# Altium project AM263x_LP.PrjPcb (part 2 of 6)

## Sheet PROC111_AM263x_2_Clock_Reset_Boot_JTAG.SchDoc
size 431 x 279 mm; Date: Not shown in title block; ApprovedBy: Not shown in title block; CheckedBy: Not shown in title block; Author: Not shown in title block; CompanyName: Not shown in title block; Engineer: Not shown in title block; Organization: Not shown in title block; Address1: Not shown in title block; Address2: Not shown in title block; Address3: Not shown in title block; Address4: Not shown in title block; DocumentNumber: 5; Revision: Use project parameter SCH_Rev; SheetNumber: 5; SheetTotal: 24; PageSetup: Record=PageOptions¦CenterHorizontal=True¦CenterVertical=True¦PrintScale=1.00¦XCorrection=1.00¦YCorrection=1.00¦PrintKind=0¦BorderSize=5000000¦LeftOffset=0¦BottomOffset=0¦Orientation=2¦PaperLength=1000¦PaperWidth=1000¦Scale=100¦PaperSource=15¦PrintQuality=600¦MediaType=1¦DitherType=10¦PaperKind=Letter¦PrintScaleMode=1
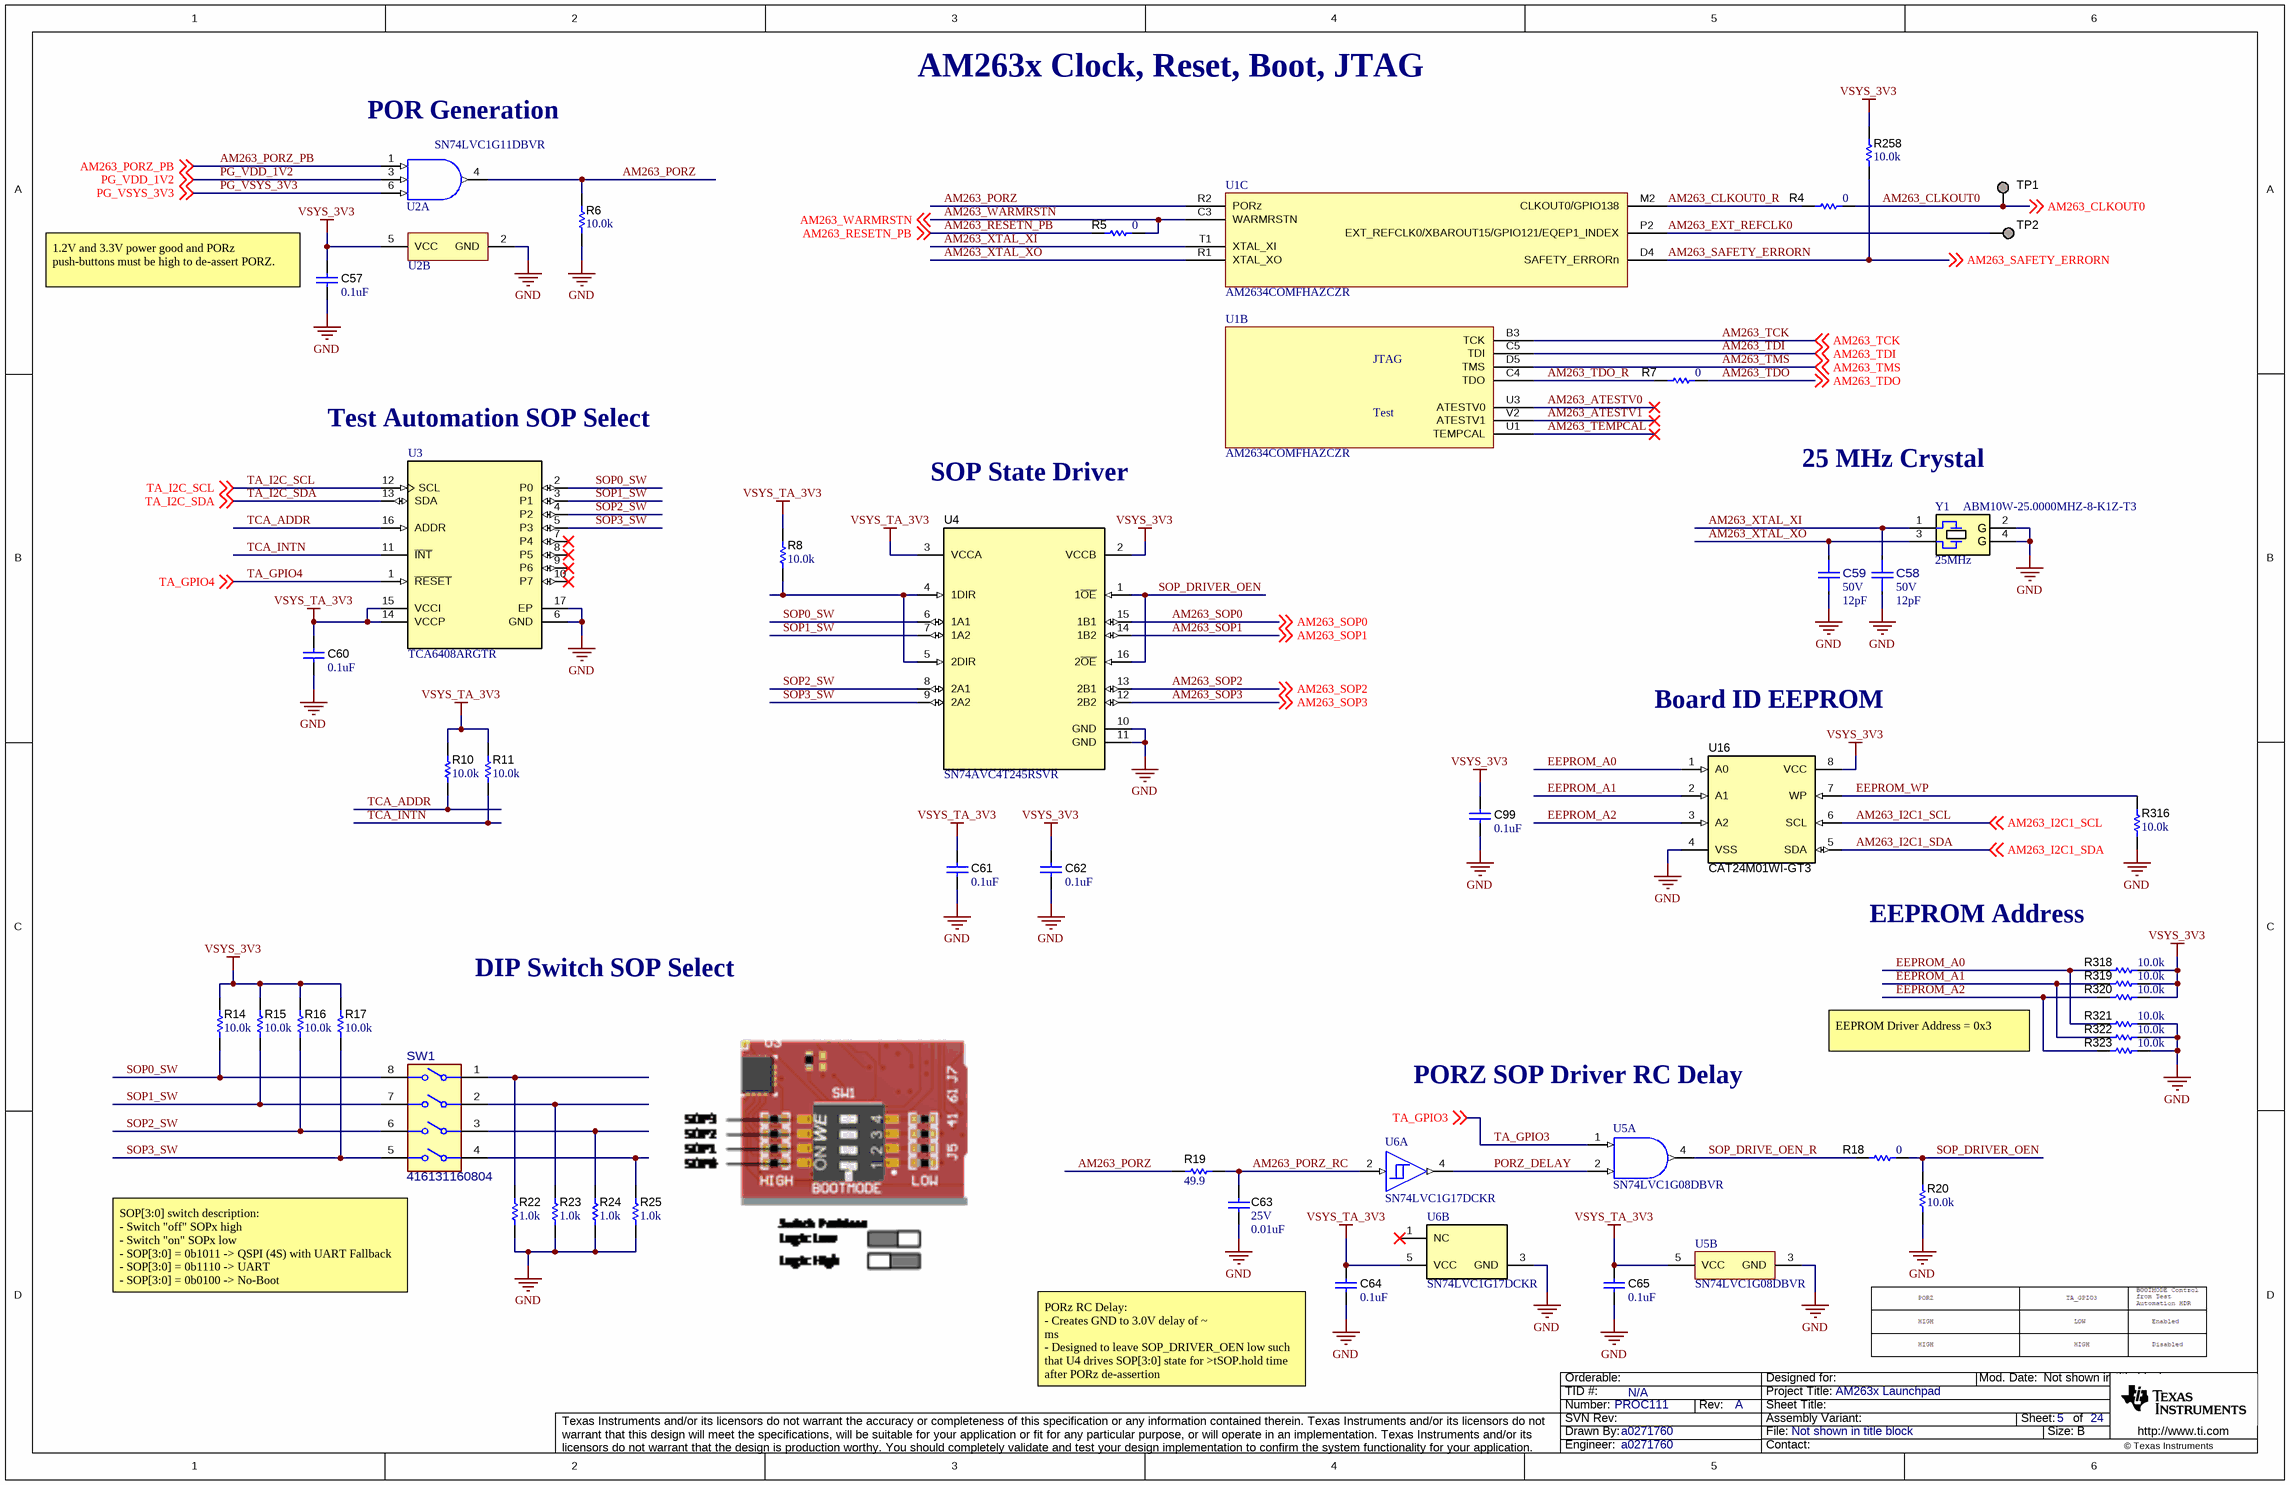
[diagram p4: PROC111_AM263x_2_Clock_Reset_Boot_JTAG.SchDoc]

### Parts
C57  ValueDisplayed: 0.1uF  [0402]  (hidden comment: GRM155R71E104KE14D)
C58  VDC_V: 50V  ValueDisplayed: 12pF  [FP-GRT1555C1H120JA02D_0402-MFG]  (hidden comment: GRT1555C1H120JA02D)
C59  VDC_V: 50V  ValueDisplayed: 12pF  [FP-GRT1555C1H120JA02D_0402-MFG]  (hidden comment: GRT1555C1H120JA02D)
C60  ValueDisplayed: 0.1uF  [0402]  (hidden comment: GRM155R71E104KE14D)
C61  ValueDisplayed: 0.1uF  [0402]  (hidden comment: GRM155R71E104KE14D)
C62  ValueDisplayed: 0.1uF  [0402]  (hidden comment: GRM155R71E104KE14D)
C63  VDC_V: 25V  ValueDisplayed: 0.01uF  [0402]  (hidden comment: GRM155R71E103KA01D)
C64  ValueDisplayed: 0.1uF  [0402]  (hidden comment: GRM155R71E104KE14D)
C65  ValueDisplayed: 0.1uF  [0402]  (hidden comment: GRM155R71E104KE14D)
C99  ValueDisplayed: 0.1uF  [0402]  (hidden comment: GRM155R71E104KE14D)
R4  value 0  [0402L]  (hidden comment: ERJ-2GE0R00X)
R5  ValueDisplayed: 0  [0402]  (hidden comment: ERJ-2GE0R00X)
R6  ValueDisplayed: 10.0k  [0402]  (hidden comment: ERJ-2RKF1002X)
R7  value 0  [0402L]  (hidden comment: ERJ-2GE0R00X)
R8  ValueDisplayed: 10.0k  [0402]  (hidden comment: ERJ-2RKF1002X)
R10  ValueDisplayed: 10.0k  [0402]  (hidden comment: ERJ-2RKF1002X)
R11  ValueDisplayed: 10.0k  [0402]  (hidden comment: ERJ-2RKF1002X)
R14  ValueDisplayed: 10.0k  [0402]  (hidden comment: ERJ-2RKF1002X)
R15  ValueDisplayed: 10.0k  [0402]  (hidden comment: ERJ-2RKF1002X)
R16  ValueDisplayed: 10.0k  [0402]  (hidden comment: ERJ-2RKF1002X)
R17  ValueDisplayed: 10.0k  [0402]  (hidden comment: ERJ-2RKF1002X)
R18  ValueDisplayed: 0  [0402]  (hidden comment: ERJ-2GE0R00X)
R19  ValueDisplayed: 49.9  [0402]  (hidden comment: ERJ-2RKF49R9X)
R20  ValueDisplayed: 10.0k  [0402]  (hidden comment: ERJ-2RKF1002X)
R22  ValueDisplayed: 1.0k  [0402]  (hidden comment: ERJ-2GEJ102X)
R23  ValueDisplayed: 1.0k  [0402]  (hidden comment: ERJ-2GEJ102X)
R24  ValueDisplayed: 1.0k  [0402]  (hidden comment: ERJ-2GEJ102X)
R25  ValueDisplayed: 1.0k  [0402]  (hidden comment: ERJ-2GEJ102X)
R258  ValueDisplayed: 10.0k  [0402]  (hidden comment: ERJ-2RKF1002X)
R316  ValueDisplayed: 10.0k  [0402]  (hidden comment: ERJ-2RKF1002X)
R318  ValueDisplayed: 10.0k  [0402]  (hidden comment: ERJ-2RKF1002X)
R319  ValueDisplayed: 10.0k  [0402]  (hidden comment: ERJ-2RKF1002X)
R320  ValueDisplayed: 10.0k  [0402]  (hidden comment: ERJ-2RKF1002X)
R321  ValueDisplayed: 10.0k  [0402]  (hidden comment: ERJ-2RKF1002X)
R322  ValueDisplayed: 10.0k  [0402]  (hidden comment: ERJ-2RKF1002X)
R323  ValueDisplayed: 10.0k  [0402]  (hidden comment: ERJ-2RKF1002X)
SW1  416131160804  [FP-416131160804_SMT_SW-MFG]
TP1  TP_SM_1MM  [TP_SM_1MM]  (value not drawn)  (no BOM)
TP2  TP_SM_1MM  [TP_SM_1MM]  (value not drawn)  (no BOM)
U1  AM2634COMFHAZCZR  [ZCZ (S-PBGA-N324)]  (parts B,C of 13)
U2  SN74LVC1G11DBVR  [DBV0006A_N]  (parts A,B of 2)
U3  TCA6408ARGTR  [RGT0016A]
U4  SN74AVC4T245RSVR  [RSV0016A]
U5  SN74LVC1G08DBVR  [DBV0005A_N]  (parts A,B of 2)
U6  SN74LVC1G17DCKR  [DCK0005A_N]  (parts A,B of 2)
U16  CAT24M01WI-GT3  [SOIC-8]
Y1  Frequency_Fixed: 25MHz  PartNumber: ABM10W-25.0000MHZ-8-K1Z-T3  [Abracon_ABM10W]  (hidden comment: ABM10W-25.0000MHZ-4-D1X-T3)

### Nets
GND: C57.1 C58.1 C59.1 C60.1 C61.1 C62.1 C63.2 C64.1 C65.1 C99.1 R6.1 R20.2 R22.1 R23.1 R24.1 R25.1 R316.2 R321.1 R322.1 R323.1 U2.2(GND) U3.6(GND) U3.17(EP) U4.10(GND) U4.11(GND) U5.3(GND) U6.3(GND) U16.4(VSS) Y1.2(GND) Y1.4(GND)
VSYS_3V3: C57.2 C62.2 C99.2 R14.1 R15.1 R16.1 R17.1 R258.2 R318.1 R319.1 R320.1 U2.5(VCC) U4.2(VCCB) U16.8(VCC)
VSYS_TA_3V3: C60.2 C61.2 C64.2 C65.2 R8.1 R10.1 R11.1 U3.14(VCCP) U3.15(VCCI) U4.3(VCCA) U5.5(VCC) U6.5(VCC)
AM263_ATESTV0: U1.U3(ATESTV0)
AM263_ATESTV1: U1.V2(ATESTV1)
AM263_CLKOUT0: R4.2 TP1.1 ; off-sheet AM263_CLKOUT0
AM263_CLKOUT0_R: R4.1 U1.M2(CLKOUT0/GPIO138)
AM263_EXT_REFCLK0: TP2.1 U1.P2(EXT_REFCLK0/XBAROUT15/GPIO121/EQEP1_INDEX)
AM263_I2C1_SCL: U16.6(SCL) ; off-sheet AM263_I2C1_SCL
AM263_I2C1_SDA: U16.5(SDA) ; off-sheet AM263_I2C1_SDA
AM263_PORZ: R6.2 R19.1 U1.R2(PORz) U2.4(Y)
AM263_PORZ_PB: U2.1(A) ; off-sheet AM263_PORZ_PB
AM263_PORZ_RC: C63.1 R19.2 U6.2(A)
AM263_RESETN_PB: R5.1 ; off-sheet AM263_RESETN_PB
AM263_SAFETY_ERRORN: R258.1 U1.D4(SAFETY_ERRORn) ; off-sheet AM263_SAFETY_ERRORN
AM263_SOP0: U4.15(1B1) ; off-sheet AM263_SOP0
AM263_SOP1: U4.14(1B2) ; off-sheet AM263_SOP1
AM263_SOP2: U4.13(2B1) ; off-sheet AM263_SOP2
AM263_SOP3: U4.12(2B2) ; off-sheet AM263_SOP3
AM263_TCK: U1.B3(TCK) ; off-sheet AM263_TCK
AM263_TDI: U1.C5(TDI) ; off-sheet AM263_TDI
AM263_TDO: R7.2 ; off-sheet AM263_TDO
AM263_TDO_R: R7.1 U1.C4(TDO)
AM263_TEMPCAL: U1.U1(TEMPCAL)
AM263_TMS: U1.D5(TMS) ; off-sheet AM263_TMS
AM263_WARMRSTN: R5.2 U1.C3(WARMRSTN) ; off-sheet AM263_WARMRSTN
AM263_XTAL_XI: C58.2 U1.T1(XTAL_XI) Y1.1
AM263_XTAL_XO: C59.2 U1.R1(XTAL_XO) Y1.3
EEPROM_A0: R318.2 R321.2 U16.1(A0)
EEPROM_A1: R319.2 R322.2 U16.2(A1)
EEPROM_A2: R320.2 R323.2 U16.3(A2)
EEPROM_WP: R316.1 U16.7(WP)
PG_VDD_1V2: U2.3(B) ; off-sheet PG_VDD_1V2
PG_VSYS_3V3: U2.6(C) ; off-sheet PG_VSYS_3V3
PORZ_DELAY: U5.2(B) U6.4(Y)
SOP0_SW: R14.2 SW1.8 U3.2(P0) U4.6(1A1)
SOP1_SW: R15.2 SW1.7 U3.3(P1) U4.7(1A2)
SOP2_SW: R16.2 SW1.6 U3.4(P2) U4.8(2A1)
SOP3_SW: R17.2 SW1.5 U3.5(P3) U4.9(2A2)
SOP_DRIVE_OEN_R: R18.1 U5.4(Y)
SOP_DRIVER_OEN: R18.2 R20.1 U4.1(1~{OE}) U4.16(2~{OE})
TA_GPIO3: U5.1(A) ; off-sheet TA_GPIO3
TA_GPIO4: U3.1(~{RESET}) ; off-sheet TA_GPIO4
TA_I2C_SCL: U3.12(SCL) ; off-sheet TA_I2C_SCL
TA_I2C_SDA: U3.13(SDA) ; off-sheet TA_I2C_SDA
TCA_ADDR: R10.2 U3.16(ADDR)
TCA_INTN: R11.2 U3.11(~{INT})
NetR8_2: R8.2 U4.4(1DIR) U4.5(2DIR)
NetR22_2: R22.2 SW1.1
NetR23_2: R23.2 SW1.2
NetR24_2: R24.2 SW1.3
NetR25_2: R25.2 SW1.4

Not connected (* = marked no-connect by the designer): U3 7(P4)* 8(P5)* 9(P6)* 10(P7)*; U6 1(NC)*

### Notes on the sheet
- AM263x Clock, Reset, Boot, JTAG
- (near U2) POR Generation
- (near C57) 1.2V and 3.3V power good and PORz push-buttons must be high to de-assert PORZ.
- Test Automation SOP Select
- SOP State Driver
- 25 MHz Crystal
- Board ID EEPROM
- EEPROM Address
- DIP Switch SOP Select
- PORZ SOP Driver RC Delay
- EEPROM Driver Address = 0x3
- (near SW1) SOP[3:0] switch description:
  - Switch "off" SOPx high
  - Switch "on" SOPx low
  - SOP[3:0] = 0b1011 -> QSPI (4S) with UART Fallback
  - SOP[3:0] = 0b1110 -> UART
  - SOP[3:0] = 0b0100 -> No-Boot
- (near C64) PORz RC Delay:
  - Creates GND to 3.0V delay of ~
  ms
  - Designed to leave SOP_DRIVER_OEN low such that U4 drives SOP[3:0] state for >tSOP.hold time after PORz de-assertion

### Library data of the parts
C57 C60-C62 C64 C65 C99 = CMP-0006659-2: CAP, CERM, 0.1 uF, 25 V, +/- 10%, X7R, 0402; Manufacturer: MuRata; TaMin_C: -55°C; Polarized: N; SizeAreaWB_mm2: 3; U/M: EA; Value: 0.1uF; TaMax_C: 125°C; SizeZ_mm: 0.6; SizeX_mm: 1; SizeY_mm: 0.5; Value2: 25V; Cap_F: 100nF; AEC Category: Q200; Value1: Unknown
C58 C59 = CMP-0120209-1: Multi-Layer Ceramic Capacitor 12pF 50V C0G ±5% 0402 Paper T/R; Manufacturer: Murata; TempCo: 30ppm/°C; SizeZ_mm: 0.55mm; AEC Qualified: Yes; AEC Grade: Grade 1
C63 = CMP-0006658-2: CAP, CERM, 0.01 uF, 25 V, +/- 10%, X7R, 0402; Manufacturer: MuRata; TaMin_C: -55°C; Polarized: N; SizeAreaWB_mm2: 3; U/M: EA; Value: 0.01uF; TaMax_C: 125°C; SizeZ_mm: 0.6; SizeX_mm: 1; SizeY_mm: 0.5; Cap_F: 10nF; AEC Category: Q200; Value1: Unknown
R4 R7 = CMP-0026992-3: RES, 0, 5%, 0.1 W, AEC-Q200 Grade 0, 0402; Manufacturer: Panasonic; Power_W: 100mW; TempCo: 600 ppm/C; Value_Code: 0000; EIA_Code: E24; SizeX_mm: 1; SizeY_mm: 0.5; SizeZ_mm: 0.6; Value2: 0.1W; AEC Qualified: Y; VDC_V: 50V; AEC Category: Q200; SizeAreaWB_mm2: 3
R5 R18 = CMP-0026992-3: RES, 0, 5%, 0.1 W, AEC-Q200 Grade 0, 0402; Manufacturer: Panasonic; Power_W: 100mW; TempCo: 600 ppm/C; Value_Code: 0000; Value: 0; EIA_Code: E24; SizeX_mm: 1; SizeY_mm: 0.5; SizeZ_mm: 0.6; Value2: 0.1W; AEC Qualified: Y; VDC_V: 50V; AEC Category: Q200; SizeAreaWB_mm2: 3
R6 R8 R10 R11 R14-R17 R20 R258 R316 R318-R323 = CMP-0026658-1: RES, 10.0 k, 1%, 0.1 W, 0402; Manufacturer: Panasonic; Power_W: 100mW; TempCo: 100 ppm/C; Value_Code: 10k0; U/M: EA; Value: 10.0k; EIA_Code: E96; Res_ohm: 10k; SizeX_mm: 1; SizeY_mm: 0.5; SizeZ_mm: 0.6; Value2: 0.1W; VDC_V: 50V; AEC Category: Q200
R19 = CMP-0026703-1: RES, 49.9, 1%, 0.1 W, AEC-Q200 Grade 0, 0402; Manufacturer: Panasonic; Power_W: 100mW; TempCo: 100 ppm/C; Value_Code: 49R9; U/M: EA; Value: 49.9; EIA_Code: E96; SizeX_mm: 1; SizeY_mm: 0.5; SizeZ_mm: 0.6; Value2: 0.1W; AEC Qualified: Y; VDC_V: 50V; AEC Grade: 0; AEC Category: Q200
R22-R25 = CMP-0078193-1: RES, 1.0 k, 5%, 0.1 W, AEC-Q200 Grade 0, 0402; Manufacturer: Panasonic; Value_Code: 1k00; SizeArea_mm2: 0.5; AEC Qualified: Y; AEC Category: Q200; Res_ohm: 1k; Value: 1.0k; SizeZ_mm: 0.6; Green_REACh: Passed; EIA_Code: E24; TempCo: 200 ppm/C; AEC Grade: 0; Power_W: 100mW; VDC_V: 50V; Value2: 0.1W; Green_Lifecycle: Active; U/M: EA; SizeX_mm: 1
SW1 = CMP-0093176-1: Dip Switch SPST 4 Position Surface Mount Slide (Standard) Actuator 25mA 24VDC; Manufacturer: Wurth; PositionCount: 4; Electromechanical Life: 1000Cycles; Circuit: 4PST; Coil Resistance_ohm: 100mΩ; VDC_V: 24V; Standoff Height: 0mm; SizeZ_mm: 2.65mm; AEC Qualified: No
TP1 TP2 = CMP-0003825-1: 1mm Test Point, SMT; Manufacturer: Any
U1 = AM263x: Sitara AM263x MCU; Manufacturer: Texas Instruments
U2 = CMP-0051219-1: Single 3-Input Positive-AND Gate, DBV0006A, LARGE T&R; Manufacturer: Texas Instruments; Output Type: CMOS; Voltage(Nom)(V): 1.8,2.5,3.3,5; ICC @ Nom Voltage(Max)(mA): 0.01; VCC(Min)(V): 1.65; Output Drive (IOL/IOH)(Max)(mA): 32/-32; Schmitt Trigger: No; Input Type: CMOS/TTL; VCC(Max)(V): 5.5; Gate Type: AND; Rating: Catalog; tpd @ Nom Voltage(Max)(ns): 20,7.8,6.2,4.6; Bits(#): 1; F @ Nom Voltage(Max)(Mhz): 150; Logic: True; Technology Family: LVC
U3 = CMP-0043157-2: Low-Voltage 8-Bit I2C and SMBus I/O Expander, 1.65 to 5.5 V, -40 to 85 degC, 16-pin QFN (RGT), Green (RoHS & no Sb/Br); Manufacturer: Texas Instruments; # of I/Os: 8; I2C Address: 0100 00x; Reset Input: Yes; Max Frequency(kHz): 400; VCC(Max)(V): 5.5; SubFamily: I2C IO Expander; VCC(Min)(V): 1.65
U4 = CMP-0066450-2: 4-Bit Dual-Supply Bus Transceiver with Configurable Voltage-Level Shifting and 3-State Outputs, RSV0016A (UQFN-16); Alternate Manufacturer: Texas Instruments; SizeAreaWB_mm2: 10.08; SizeZ_mm: 0.55; SizeX_mm: 1.8; SizeY_mm: 2.6; SizeArea_mm2: 4.68; CompType: IC; AEC Category: Q200; AEC Qualified: N
U5 = CMP-0051588-2: Single 2-Input Positive-AND Gate, DBV0005A, LARGE T&R; Manufacturer: Texas Instruments; Logic: True; ICC @ Nom Voltage(Max)(mA): 0.01; VCC(Min)(V): 1.65; Bits(#): 1; Rating: Catalog; Schmitt Trigger: No; Voltage(Nom)(V): 1.8,2.5,3.3,5; Output Drive (IOL/IOH)(Max)(mA): 32/-32; Gate Type: AND; tpd @ Nom Voltage(Max)(ns): 4.5,6,4,5; VCC(Max)(V): 5.5; Output Type: CMOS; F @ Nom Voltage(Max)(Mhz): 150; Input Type: CMOS/TTL; Technology Family: LVC; AEC Category: Q200; AEC Qualified: N; CompType: IC
U6 = CMP-0051704-3: Single Schmitt-Trigger Buffer, DCK0005A, LARGE T&R; Manufacturer: Texas Instruments; tpd @ Nom Voltage(Max)(ns): 11,6.5,5.5,5; Bits(#): 1; VCC(Min)(V): 1.65; F @ Nom Voltage(Max)(Mhz): 150; VCC(Max)(V): 5.5; Input Type: CMOS/TTL; Sub-Family: Non-Inverting Buffer/Driver; Output Type: CMOS; Output Drive (IOL/IOH)(Max)(mA): 32/-32; 3-State Output: No; Logic: True; ICC @ Nom Voltage(Max)(mA): 0.01; Voltage(Nom)(V): 1.8,2.5,3.3,5; Rating: Catalog; Schmitt Trigger: Yes; Technology Family: LVC; AEC Category: Q200; AEC Qualified: N; CompType: IC; SizeAreaWB_mm2: 9.3; SizeArea_mm2: 4.2; SizeX_mm: 2.1; SizeY_mm: 2.0; SizeZ_mm: 1.1
U16 = CMP-0005327-2: 1024-Kb I2C CMOS Serial EEPROM, SOIC-8; Manufacturer: ON Semiconductor; SizeAreaWB_mm2: 55.131; SizeZ_mm: 1.75; SizeX_mm: 5.99; SizeY_mm: 4.9; SizeArea_mm2: 29.351
Y1 = CMP-0084811-1: Crystal, 25 MHz, 10 ppm, 4 pF, SMD; Manufacturer: Abracon Corporation; Load Capacitance: 4 pF; TaMax_C: 85°C; SizeY_mm: 2.5; SizeAreaWB_mm2: 10.5; AEC Category: Q200; Frequency Stability: 20 ppm; SizeX_mm: 2; SizeArea_mm2: 5; SizeZ_mm: 0.6; AEC Qualified: N; TaMin_C: -40°C; Frequency Tolerance: 10 ppm

## Sheet PROC111_AM263x_Serial_Connectivity.SchDoc: XDS110 JTAG/USB-to-UART Bridge
size 431 x 279 mm; Date: Not shown in title block; ApprovedBy: Not shown in title block; CheckedBy: Not shown in title block; Author: Not shown in title block; CompanyName: Not shown in title block; Engineer: Not shown in title block; Organization: Not shown in title block; Address1: Not shown in title block; Address2: Not shown in title block; Address3: Not shown in title block; Address4: Not shown in title block; DocumentNumber: 6; Revision: Use project parameter SCH_Rev; SheetNumber: 6; SheetTotal: 24; PageSetup: Record=PageOptions¦CenterHorizontal=True¦CenterVertical=True¦PrintScale=1.00¦XCorrection=1.00¦YCorrection=1.00¦PrintKind=0¦BorderSize=5000000¦LeftOffset=0¦BottomOffset=0¦Orientation=2¦PaperLength=1000¦PaperWidth=1000¦Scale=100¦PaperSource=15¦PrintQuality=600¦MediaType=1¦DitherType=10¦PaperKind=Letter¦PrintScaleMode=1
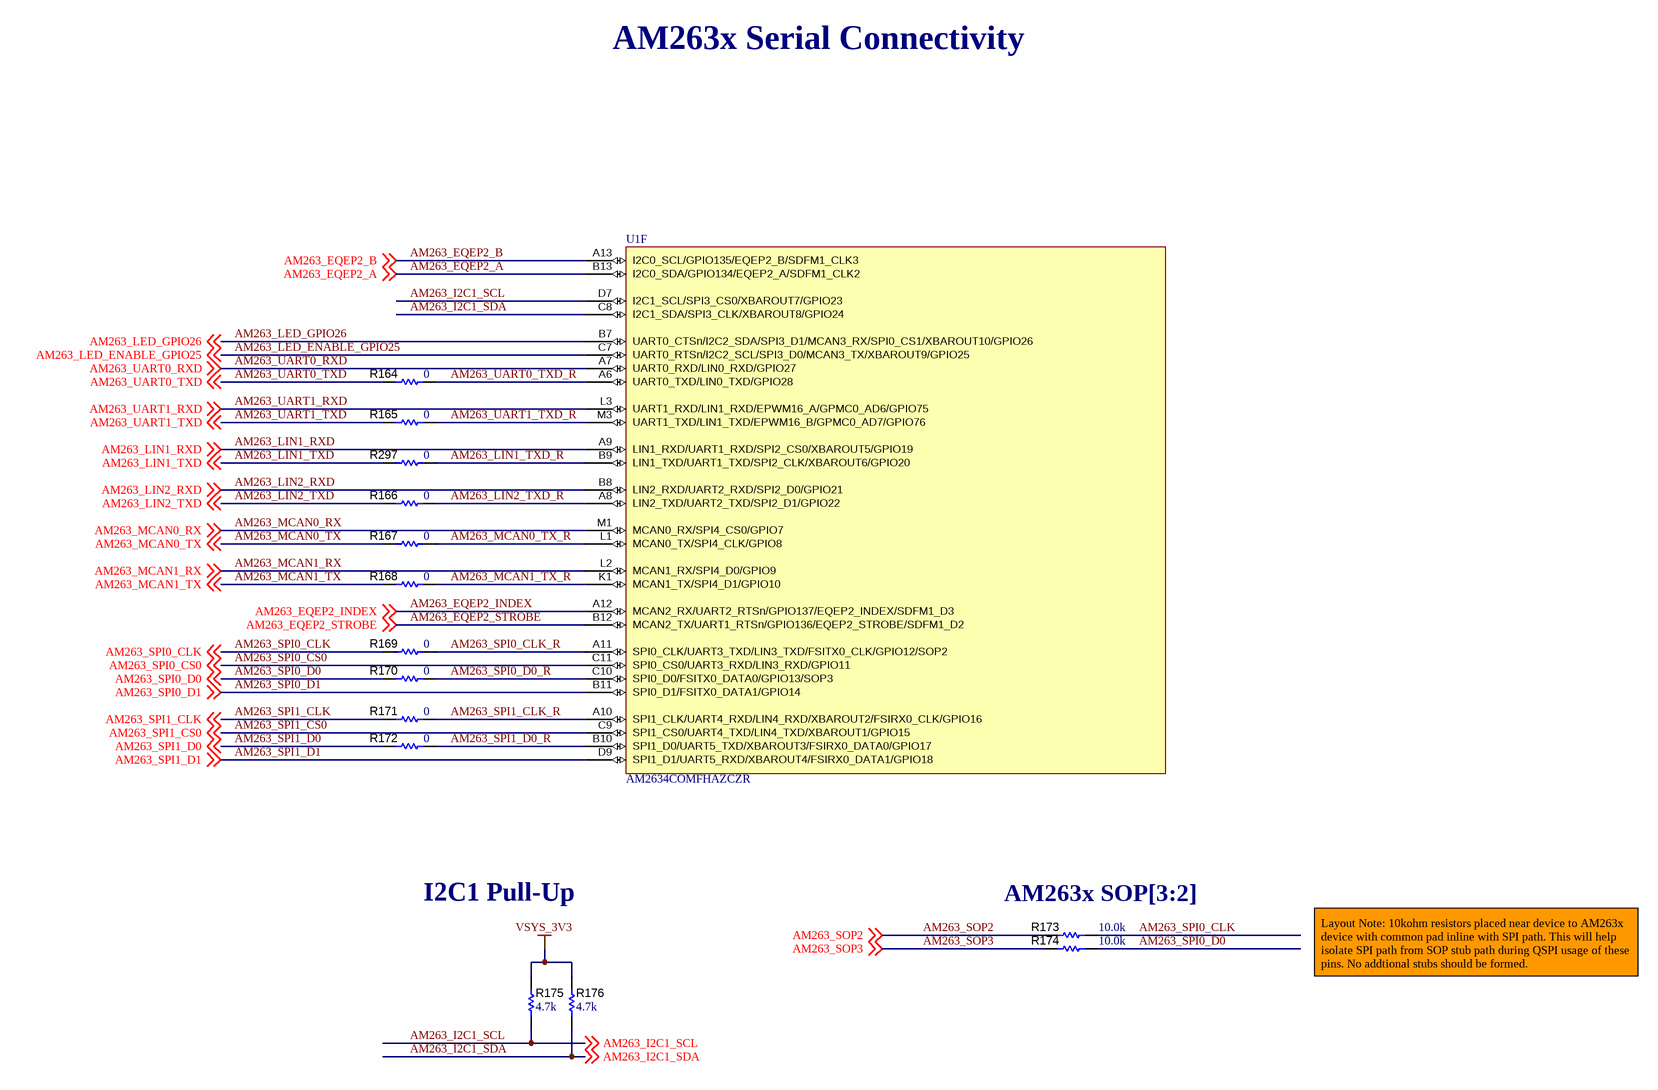
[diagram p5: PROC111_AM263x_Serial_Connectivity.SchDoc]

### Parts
R164  value 0  [0402L]  (hidden comment: ERJ-2GE0R00X)
R165  value 0  [0402L]  (hidden comment: ERJ-2GE0R00X)
R166  value 0  [0402L]  (hidden comment: ERJ-2GE0R00X)
R167  value 0  [0402L]  (hidden comment: ERJ-2GE0R00X)
R168  value 0  [0402L]  (hidden comment: ERJ-2GE0R00X)
R169  value 0  [0402L]  (hidden comment: ERJ-2GE0R00X)
R170  value 0  [0402L]  (hidden comment: ERJ-2GE0R00X)
R171  value 0  [0402L]  (hidden comment: ERJ-2GE0R00X)
R172  value 0  [0402L]  (hidden comment: ERJ-2GE0R00X)
R173  ValueDisplayed: 10.0k  [0402]  (hidden comment: ERJ-2RKF1002X)
R174  ValueDisplayed: 10.0k  [0402]  (hidden comment: ERJ-2RKF1002X)
R175  ValueDisplayed: 4.7k  [0402]  (hidden comment: CRCW04024K70JNED)
R176  ValueDisplayed: 4.7k  [0402]  (hidden comment: CRCW04024K70JNED)
R297  value 0  [0402L]  (hidden comment: ERJ-2GE0R00X)
U1  AM2634COMFHAZCZR  [ZCZ (S-PBGA-N324)]  (part F of 13)

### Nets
VSYS_3V3: R175.2 R176.2
AM263_EQEP2_A: U1.B13(I2C0_SDA/GPIO134/EQEP2_A/SDFM1_CLK2) ; off-sheet AM263_EQEP2_A
AM263_EQEP2_B: U1.A13(I2C0_SCL/GPIO135/EQEP2_B/SDFM1_CLK3) ; off-sheet AM263_EQEP2_B
AM263_EQEP2_INDEX: U1.A12(MCAN2_RX/UART2_RTSn/GPIO137/EQEP2_INDEX/SDFM1_D3) ; off-sheet AM263_EQEP2_INDEX
AM263_EQEP2_STROBE: U1.B12(MCAN2_TX/UART1_RTSn/GPIO136/EQEP2_STROBE/SDFM1_D2) ; off-sheet AM263_EQEP2_STROBE
AM263_I2C1_SCL: R175.1 U1.D7(I2C1_SCL/SPI3_CS0/XBAROUT7/GPIO23) ; off-sheet AM263_I2C1_SCL
AM263_I2C1_SDA: R176.1 U1.C8(I2C1_SDA/SPI3_CLK/XBAROUT8/GPIO24) ; off-sheet AM263_I2C1_SDA
AM263_LED_ENABLE_GPIO25: U1.C7(UART0_RTSn/I2C2_SCL/SPI3_D0/MCAN3_TX/XBAROUT9/GPIO25) ; off-sheet AM263_LED_ENABLE_GPIO25
AM263_LED_GPIO26: U1.B7(UART0_CTSn/I2C2_SDA/SPI3_D1/MCAN3_RX/SPI0_CS1/XBAROUT10/GPIO26) ; off-sheet AM263_LED_GPIO26
AM263_LIN1_RXD: U1.A9(LIN1_RXD/UART1_RXD/SPI2_CS0/XBAROUT5/GPIO19) ; off-sheet AM263_LIN1_RXD
AM263_LIN1_TXD: R297.1 ; off-sheet AM263_LIN1_TXD
AM263_LIN1_TXD_R: R297.2 U1.B9(LIN1_TXD/UART1_TXD/SPI2_CLK/XBAROUT6/GPIO20)
AM263_LIN2_RXD: U1.B8(LIN2_RXD/UART2_RXD/SPI2_D0/GPIO21) ; off-sheet AM263_LIN2_RXD
AM263_LIN2_TXD: R166.1 ; off-sheet AM263_LIN2_TXD
AM263_LIN2_TXD_R: R166.2 U1.A8(LIN2_TXD/UART2_TXD/SPI2_D1/GPIO22)
AM263_MCAN0_RX: U1.M1(MCAN0_RX/SPI4_CS0/GPIO7) ; off-sheet AM263_MCAN0_RX
AM263_MCAN0_TX: R167.1 ; off-sheet AM263_MCAN0_TX
AM263_MCAN0_TX_R: R167.2 U1.L1(MCAN0_TX/SPI4_CLK/GPIO8)
AM263_MCAN1_RX: U1.L2(MCAN1_RX/SPI4_D0/GPIO9) ; off-sheet AM263_MCAN1_RX
AM263_MCAN1_TX: R168.1 ; off-sheet AM263_MCAN1_TX
AM263_MCAN1_TX_R: R168.2 U1.K1(MCAN1_TX/SPI4_D1/GPIO10)
AM263_SOP2: R173.2 ; off-sheet AM263_SOP2
AM263_SOP3: R174.2 ; off-sheet AM263_SOP3
AM263_SPI0_CLK: R169.1 R173.1 ; off-sheet AM263_SPI0_CLK
AM263_SPI0_CLK_R: R169.2 U1.A11(SPI0_CLK/UART3_TXD/LIN3_TXD/FSITX0_CLK/GPIO12/SOP2)
AM263_SPI0_CS0: U1.C11(SPI0_CS0/UART3_RXD/LIN3_RXD/GPIO11) ; off-sheet AM263_SPI0_CS0
AM263_SPI0_D0: R170.1 R174.1 ; off-sheet AM263_SPI0_D0
AM263_SPI0_D0_R: R170.2 U1.C10(SPI0_D0/FSITX0_DATA0/GPIO13/SOP3)
AM263_SPI0_D1: U1.B11(SPI0_D1/FSITX0_DATA1/GPIO14) ; off-sheet AM263_SPI0_D1
AM263_SPI1_CLK: R171.1 ; off-sheet AM263_SPI1_CLK
AM263_SPI1_CLK_R: R171.2 U1.A10(SPI1_CLK/UART4_RXD/LIN4_RXD/XBAROUT2/FSIRX0_CLK/GPIO16)
AM263_SPI1_CS0: U1.C9(SPI1_CS0/UART4_TXD/LIN4_TXD/XBAROUT1/GPIO15) ; off-sheet AM263_SPI1_CS0
AM263_SPI1_D0: R172.1 ; off-sheet AM263_SPI1_D0
AM263_SPI1_D0_R: R172.2 U1.B10(SPI1_D0/UART5_TXD/XBAROUT3/FSIRX0_DATA0/GPIO17)
AM263_SPI1_D1: U1.D9(SPI1_D1/UART5_RXD/XBAROUT4/FSIRX0_DATA1/GPIO18) ; off-sheet AM263_SPI1_D1
AM263_UART0_RXD: U1.A7(UART0_RXD/LIN0_RXD/GPIO27) ; off-sheet AM263_UART0_RXD
AM263_UART0_TXD: R164.1 ; off-sheet AM263_UART0_TXD
AM263_UART0_TXD_R: R164.2 U1.A6(UART0_TXD/LIN0_TXD/GPIO28)
AM263_UART1_RXD: U1.L3(UART1_RXD/LIN1_RXD/EPWM16_A/GPMC0_AD6/GPIO75) ; off-sheet AM263_UART1_RXD
AM263_UART1_TXD: R165.1 ; off-sheet AM263_UART1_TXD
AM263_UART1_TXD_R: R165.2 U1.M3(UART1_TXD/LIN1_TXD/EPWM16_B/GPMC0_AD7/GPIO76)

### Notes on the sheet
- AM263x Serial Connectivity
- I2C1 Pull-Up
- AM263x SOP[3:2]
- Layout Note: 10kohm resistors placed near device to AM263x device with common pad inline with SPI path. This will help isolate SPI path from SOP stub path during QSPI usage of these pins. No addtional stubs should be formed.

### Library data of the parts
R164-R172 R297 = CMP-0026992-3: as R4 on sheet PROC111_AM263x_2_Clock_Reset_Boot_JTAG
R173 R174 = CMP-0026658-1: as R6 on sheet PROC111_AM263x_2_Clock_Reset_Boot_JTAG
R175 R176 = CMP-0026938-5: RES, 4.7 k, 5%, 0.063 W, AEC-Q200 Grade 0, 0402; Manufacturer: Vishay-Dale; Power_W: 63mW; TempCo: 200 ppm/C; Value_Code: 4k70; Value: 4.7k; EIA_Code: E24; SizeX_mm: 1; SizeY_mm: 0.5; SizeZ_mm: 0.6; Value2: 0.063W; AEC Qualified: Y; VDC_V: 50V; AEC Category: Q200; AEC Grade: 0
U1 = AM263x: as U1 on sheet PROC111_AM263x_2_Clock_Reset_Boot_JTAG

## Sheet PROC111_AM263x_3_QSPI_MMC.SchDoc
size 431 x 279 mm; Date: Not shown in title block; ApprovedBy: Not shown in title block; CheckedBy: Not shown in title block; Author: Not shown in title block; CompanyName: Not shown in title block; Engineer: Not shown in title block; Organization: Not shown in title block; Address1: Not shown in title block; Address2: Not shown in title block; Address3: Not shown in title block; Address4: Not shown in title block; DocumentNumber: 7; Revision: Use project parameter SCH_Rev; SheetNumber: 7; SheetTotal: 24; PageSetup: Record=PageOptions¦CenterHorizontal=True¦CenterVertical=True¦PrintScale=1.00¦XCorrection=1.00¦YCorrection=1.00¦PrintKind=0¦BorderSize=5000000¦LeftOffset=0¦BottomOffset=0¦Orientation=2¦PaperLength=1000¦PaperWidth=1000¦Scale=100¦PaperSource=15¦PrintQuality=600¦MediaType=1¦DitherType=10¦PaperKind=Letter¦PrintScaleMode=1
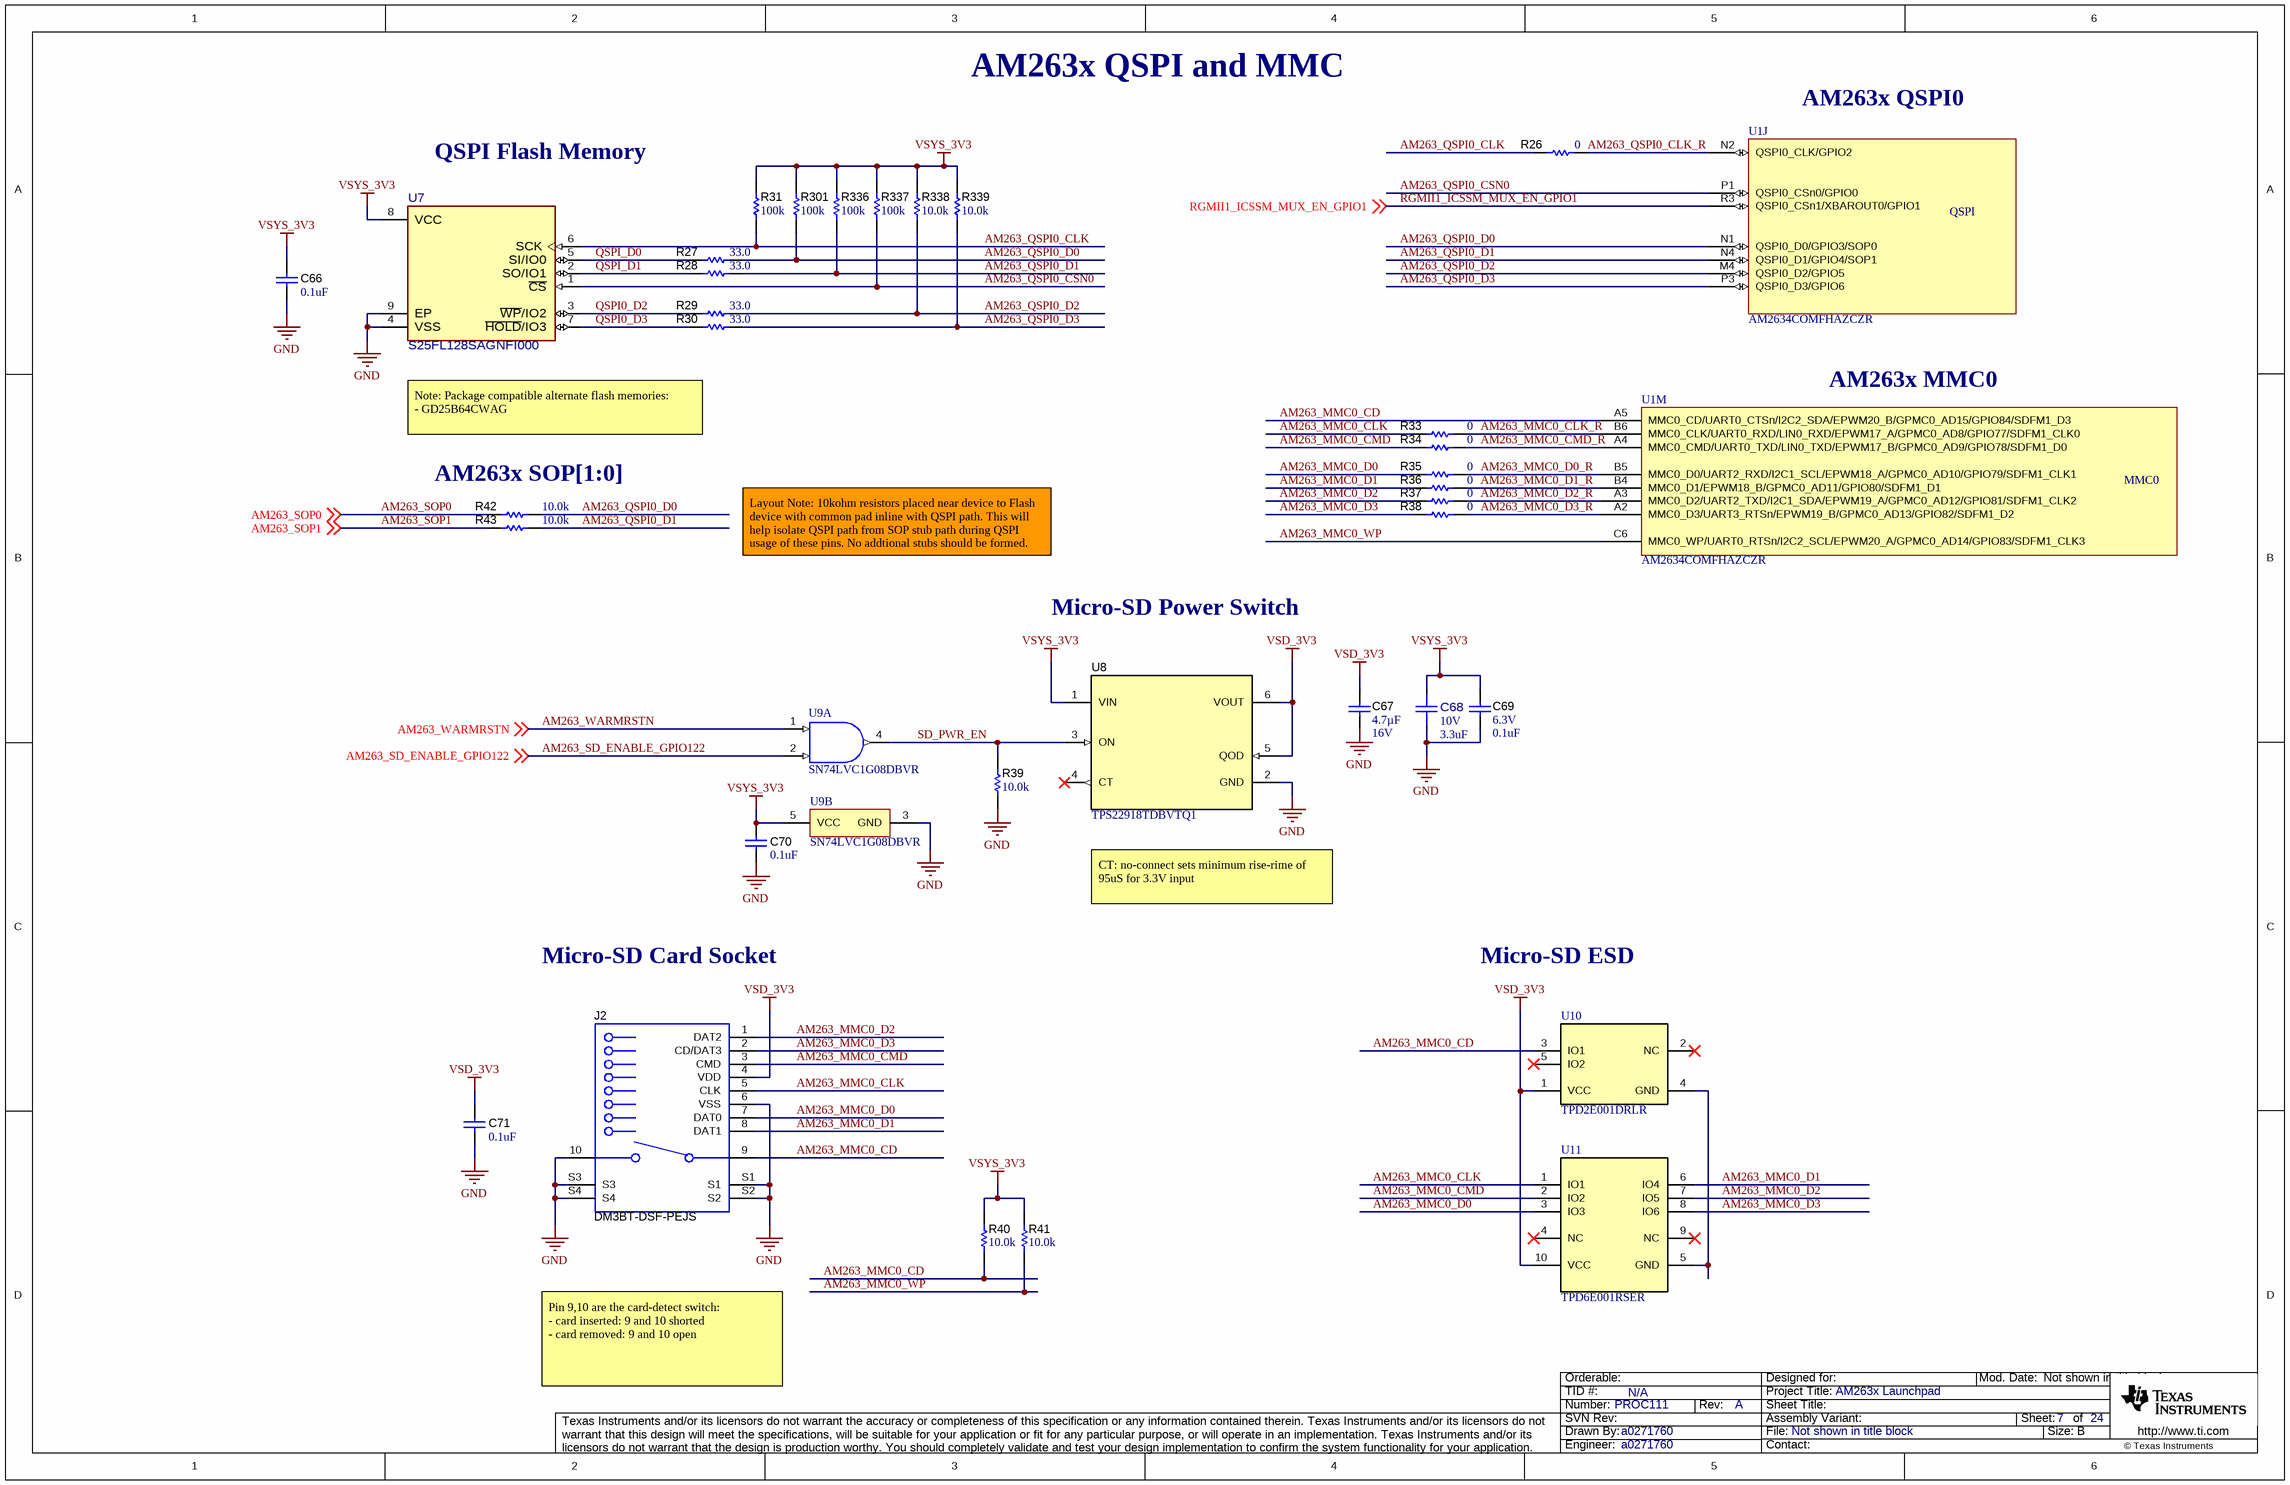
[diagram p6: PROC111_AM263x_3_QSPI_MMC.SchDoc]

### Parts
C66  ValueDisplayed: 0.1uF  [0402]  (hidden comment: GRM155R71E104KE14D)
C67  Cap_F: 4.7µF  VDC_V: 16V  [0603]  (hidden comment: GRM188Z71C475KE21D)
C68  VDC_V: 10V  ValueDisplayed: 3.3uF  [FP-CL10A335KP8NNNC_0603-MFG]  (hidden comment: CL10A335KP8NNNC)
C69  VDC_V: 6.3V  ValueDisplayed: 0.1uF  [0402]  (hidden comment: GRM155R70J104KA01D)
C70  ValueDisplayed: 0.1uF  [0402]  (hidden comment: GRM155R71E104KE14D)
C71  ValueDisplayed: 0.1uF  [0402]  (hidden comment: GRM155R71E104KE14D)
J2  DM3BT-DSF-PEJS  [Hirose_DM3BT-DSF-PEJS]
R26  value 0  [0402L]  (hidden comment: ERJ-2GE0R00X)
R27  ValueDisplayed: 33.0  [0402S]  (hidden comment: ERJ-2RKF33R0X)
R28  ValueDisplayed: 33.0  [0402S]  (hidden comment: ERJ-2RKF33R0X)
R29  ValueDisplayed: 33.0  [0402S]  (hidden comment: ERJ-2RKF33R0X)
R30  ValueDisplayed: 33.0  [0402S]  (hidden comment: ERJ-2RKF33R0X)
R31  ValueDisplayed: 100k  [0402S]  (hidden comment: ERJ-2RKF1003X)
R33  ValueDisplayed: 0  [0402L]  (hidden comment: ERJ-2GE0R00X)
R34  ValueDisplayed: 0  [0402L]  (hidden comment: ERJ-2GE0R00X)
R35  ValueDisplayed: 0  [0402L]  (hidden comment: ERJ-2GE0R00X)
R36  ValueDisplayed: 0  [0402L]  (hidden comment: ERJ-2GE0R00X)
R37  ValueDisplayed: 0  [0402L]  (hidden comment: ERJ-2GE0R00X)
R38  ValueDisplayed: 0  [0402L]  (hidden comment: ERJ-2GE0R00X)
R39  ValueDisplayed: 10.0k  [0402L]  (hidden comment: CRCW040210K0FKED)
R40  ValueDisplayed: 10.0k  [0402L]  (hidden comment: CRCW040210K0FKED)
R41  ValueDisplayed: 10.0k  [0402L]  (hidden comment: CRCW040210K0FKED)
R42  ValueDisplayed: 10.0k  [0402]  (hidden comment: ERJ-2RKF1002X)
R43  ValueDisplayed: 10.0k  [0402]  (hidden comment: ERJ-2RKF1002X)
R301  ValueDisplayed: 100k  [0402S]  (hidden comment: ERJ-2RKF1003X)
R336  ValueDisplayed: 100k  [0402S]  (hidden comment: ERJ-2RKF1003X)
R337  ValueDisplayed: 100k  [0402S]  (hidden comment: ERJ-2RKF1003X)
R338  ValueDisplayed: 10.0k  [0402S]  (hidden comment: CRCW040210K0FKED)
R339  ValueDisplayed: 10.0k  [0402S]  (hidden comment: CRCW040210K0FKED)
U1  AM2634COMFHAZCZR  [ZCZ (S-PBGA-N324)]  (parts J,M of 13)
U7  S25FL128SAGNFI000  [FP-S25FL128SAGNFI000_WSON8-IPC_B]
U8  TPS22918TDBVTQ1  [DBV0006A_N]
U9  SN74LVC1G08DBVR  [DBV0005A_N]  (parts A,B of 2)
U10  TPD2E001DRLR  [DRL0005A]
U11  TPD6E001RSER  [RSE0010A]

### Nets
GND: C66.1 C67.2 C68.1 C69.2 C70.1 C71.1 J2.6(VSS) J2.10(B) J2.S1 J2.S2 J2.S3 J2.S4 R39.1 U7.4(VSS) U7.9(EP) U8.2(GND) U9.3(GND)
VSD_3V3: C67.1 C71.2 J2.4(VDD) U8.5(QOD) U8.6(VOUT) U10.1(VCC) U11.10(VCC)
VSYS_3V3: C66.2 C68.2 C69.1 C70.2 R31.2 R40.2 R41.2 R301.2 R336.2 R337.2 R338.2 R339.2 U7.8(VCC) U8.1(VIN) U9.5(VCC)
AM263_MMC0_CD: J2.9(A) R40.1 U1.A5(MMC0_CD/UART0_CTSn/I2C2_SDA/EPWM20_B/GPMC0_AD15/GPIO84/SDFM1_D3) U10.3(IO1)
AM263_MMC0_CLK: J2.5(CLK) R33.2 U11.1(IO1)
AM263_MMC0_CLK_R: R33.1 U1.B6(MMC0_CLK/UART0_RXD/LIN0_RXD/EPWM17_A/GPMC0_AD8/GPIO77/SDFM1_CLK0)
AM263_MMC0_CMD: J2.3(CMD) R34.2 U11.2(IO2)
AM263_MMC0_CMD_R: R34.1 U1.A4(MMC0_CMD/UART0_TXD/LIN0_TXD/EPWM17_B/GPMC0_AD9/GPIO78/SDFM1_D0)
AM263_MMC0_D0: J2.7(DAT0) R35.2 U11.3(IO3)
AM263_MMC0_D0_R: R35.1 U1.B5(MMC0_D0/UART2_RXD/I2C1_SCL/EPWM18_A/GPMC0_AD10/GPIO79/SDFM1_CLK1)
AM263_MMC0_D1: J2.8(DAT1) R36.2 U11.6(IO4)
AM263_MMC0_D1_R: R36.1 U1.B4(MMC0_D1/EPWM18_B/GPMC0_AD11/GPIO80/SDFM1_D1)
AM263_MMC0_D2: J2.1(DAT2) R37.2 U11.7(IO5)
AM263_MMC0_D2_R: R37.1 U1.A3(MMC0_D2/UART2_TXD/I2C1_SDA/EPWM19_A/GPMC0_AD12/GPIO81/SDFM1_CLK2)
AM263_MMC0_D3: J2.2(CD/DAT3) R38.2 U11.8(IO6)
AM263_MMC0_D3_R: R38.1 U1.A2(MMC0_D3/UART3_RTSn/EPWM19_B/GPMC0_AD13/GPIO82/SDFM1_D2)
AM263_MMC0_WP: R41.1 U1.C6(MMC0_WP/UART0_RTSn/I2C2_SCL/EPWM20_A/GPMC0_AD14/GPIO83/SDFM1_CLK3)
AM263_QSPI0_CLK: R26.1 R31.1 U7.6(SCK)
AM263_QSPI0_CLK_R: R26.2 U1.N2(QSPI0_CLK/GPIO2)
AM263_QSPI0_CSN0: R337.1 U1.P1(QSPI0_CSn0/GPIO0) U7.1(~{CS})
AM263_QSPI0_D0: R27.2 R42.1 R301.1 U1.N1(QSPI0_D0/GPIO3/SOP0)
AM263_QSPI0_D1: R28.2 R43.1 R336.1 U1.N4(QSPI0_D1/GPIO4/SOP1)
AM263_QSPI0_D2: R29.2 R338.1 U1.M4(QSPI0_D2/GPIO5)
AM263_QSPI0_D3: R30.2 R339.1 U1.P3(QSPI0_D3/GPIO6)
AM263_SD_ENABLE_GPIO122: U9.2(B) ; off-sheet AM263_SD_ENABLE_GPIO122
AM263_SOP0: R42.2 ; off-sheet AM263_SOP0
AM263_SOP1: R43.2 ; off-sheet AM263_SOP1
AM263_WARMRSTN: U9.1(A) ; off-sheet AM263_WARMRSTN
QSPI0_D2: R29.1 U7.3(~{WP}/IO2)
QSPI0_D3: R30.1 U7.7(~{HOLD}/IO3)
QSPI_D0: R27.1 U7.5(SI/IO0)
QSPI_D1: R28.1 U7.2(SO/IO1)
RGMII1_ICSSM_MUX_EN_GPIO1: U1.R3(QSPI0_CSn1/XBAROUT0/GPIO1) ; off-sheet RGMII1_ICSSM_MUX_EN_GPIO1
SD_PWR_EN: R39.2 U8.3(ON) U9.4(Y)
NetU10_4: U10.4(GND) U11.5(GND)

Not connected (* = marked no-connect by the designer): U8 4(CT)*; U10 2(NC)* 5(IO2)*; U11 4(NC)* 9(NC)*

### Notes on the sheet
- AM263x QSPI and MMC
- QSPI Flash Memory
- AM263x QSPI0
- Note: Package compatible alternate flash memories:
  - GD25B64CWAG
- AM263x MMC0
- AM263x SOP[1:0]
- Layout Note: 10kohm resistors placed near device to Flash device with common pad inline with QSPI path. This will help isolate QSPI path from SOP stub path during QSPI usage of these pins. No addtional stubs should be formed.
- Micro-SD Power Switch
- CT: no-connect sets minimum rise-rime of 95uS for 3.3V input
- Micro-SD Card Socket
- Micro-SD ESD
- Pin 9,10 are the card-detect switch:
  - card inserted: 9 and 10 shorted
  - card removed: 9 and 10 open

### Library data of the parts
C66 C70 C71 = CMP-0006659-2: as C57 on sheet PROC111_AM263x_2_Clock_Reset_Boot_JTAG
C67 = CMP-0064936-4: CAP, CERM, 4.7 uF, 16 V,+/- 10%, X7R, 0603; Manufacturer: MuRata; TaMin_C: -55°C; Polarized: N; SizeAreaWB_mm2: 4.68; Value1: Unknown; U/M: EA; Value: 4.7uF; TaMax_C: 125°C; SizeZ_mm: 1; SizeX_mm: 1.6; SizeY_mm: 0.8; SizeArea_mm2: 1.28; AEC Category: Q200
C68 = CMP-0042976-1: Cap Ceramic 3.3uF 10V X5R ±10% Pad SMD 0603 +85°C T/R; Manufacturer: Samsung; TempCo: 15%; Value: 3.3µF; SizeZ_mm: 0.9mm; AEC Qualified: No
C69 = CMP-0006623-2: CAP, CERM, 0.1 uF, 6.3 V, +/- 10%, X7R, 0402; Manufacturer: MuRata; TaMin_C: -55°C; Polarized: N; SizeAreaWB_mm2: 3; Value1: Unknown; U/M: EA; Value: 0.1uF; TaMax_C: 125°C; SizeZ_mm: 0.6; SizeX_mm: 1; SizeY_mm: 0.5; Cap_F: 100nF; AEC Category: Q200
J2 = CMP-0080007-1: Conncetor, micro SD, 8+2 Pos, R/A, SMT; Manufacturer: Hirose Electric Co. Ltd.; Pitch_mm: 1.1; Gender: Female; ContactFinish: Gold; Row_Count: 1; CompType: Connector
R26 = CMP-0026992-3: as R4 on sheet PROC111_AM263x_2_Clock_Reset_Boot_JTAG
R27-R30 = CMP-0026696-1: RES, 33.0, 1%, 0.1 W, 0402; Manufacturer: Panasonic; Power_W: 100mW; TempCo: 100 ppm/C; Value_Code: 33R0; U/M: EA; Value: 33.0; Res_ohm: 33; SizeX_mm: 1; SizeY_mm: 0.5; SizeZ_mm: 0.6; Value2: 0.1W; VDC_V: 50V; AEC Category: Q200
R31 R301 R336 R337 = CMP-0026659-2: RES, 100 k, 1%, 0.1 W, 0402; Manufacturer: Panasonic; U/M: EA; Value2: 0.1W; EIA_Code: E96; Value: 100k; SizeArea_mm2: 0.5; TempCo: 100 ppm/C; SizeZ_mm: 0.6; AEC Category: Q200; VDC_V: 50V; Power_W: 100mW; AEC Grade: 0; SizeX_mm: 1; AEC Qualified: Yes
R33-R38 = CMP-0026992-3: as R5 on sheet PROC111_AM263x_2_Clock_Reset_Boot_JTAG
R39-R41 R338 R339 = CMP-0025958-3: RES, 10.0 k, 1%, 0.063 W, AEC-Q200 Grade 0, 0402; Manufacturer: Vishay-Dale; Power_W: 63mW; TempCo: 100 ppm/C; Value_Code: 10k0; Value: 10.0k; EIA_Code: E96; Res_ohm: 10k; SizeX_mm: 1; SizeY_mm: 0.5; SizeZ_mm: 0.6; Value2: 0.063W; AEC Qualified: Y; VDC_V: 50V; AEC Category: Q200; AEC Grade: 0
R42 R43 = CMP-0026658-1: as R6 on sheet PROC111_AM263x_2_Clock_Reset_Boot_JTAG
U1 = AM263x: as U1 on sheet PROC111_AM263x_2_Clock_Reset_Boot_JTAG
U7 = CMP-0093537-1: FLASH - NOR Memory IC 128Mb (16M x 8) SPI - Quad I/O 133 MHz 8-WSON (6x8); Manufacturer: Cypress Semiconductor; Nominal Supply Current: 16-100mA; AEC Qualified: No; Max Supply Voltage: 3.6V; Access Time: 8ns; TaMin_C: -40°C; SizeZ_mm: 0.8mm; TaMax_C: +85°C; Standoff Height: 0mm; Memory Size: 128Mbits; Min Supply Voltage: 1.65V; Frequency_Fixed: 133MHz
U8 = CMP-0081995-1: 5.5V, 2A, 52mΩ Automotive High-Side Load Switch with Adjustable Rise Time & Quick Output Discharge, DBV0006A (SOT-23-6); Alternate PartNumber: TPS22918TDBVRQ1; Alternate Manufacturer: Texas Instruments; SizeAreaWB_mm2: 14.82; SizeZ_mm: 1.45; SizeX_mm: 2.8; SizeY_mm: 2.9; SizeArea_mm2: 8.12; CompType: IC; AEC Qualified: Y; AEC Category: Q200
U9 = CMP-0051588-2: as U5 on sheet PROC111_AM263x_2_Clock_Reset_Boot_JTAG
U10 = CMP-0043096-2: Low-Capacitance + / - 15 kV ESD-Protection Array for High-Speed Data Interfaces, 2 Channels, -40 to +85 degC, 5-pin SOT (DRL), Green (RoHS & no Sb/Br); Manufacturer: Texas Instruments; IO Leakage Current(nA): 1; IO Capacitance(Typ)(pF): 1.5; USB High Speed: TRUE; SubFamily: ESD Solution; Breakdown Voltage(Min)(V): 11; IEC 61000-4-2 Air-Gap(+/- kV): 15; IEC 61000-4-2 Contact(+/- kV): 8
U11 = CMP-0043123-1: Low-Capacitance + / - 15 kV ESD Protection Array for High-Speed Data Interfaces, 6 Channels, -40 to +85 degC, 10-pin UQFN (RSE), Green (RoHS & no Sb/Br); Manufacturer: Texas Instruments; Serial ATA / eSATA: TRUE; IO Leakage Current(nA): 1; IO Capacitance(Typ)(pF): 1.5; IEC 61000-4-2 Contact(+/- kV): 8; Breakdown Voltage(Min)(V): 11; IEC 61000-4-2 Air-Gap(+/- kV): 15; SubFamily: ESD Solution

## Sheet PROC111_AM263x_4_ADC_DAC.SchDoc
size 431 x 279 mm; Date: Not shown in title block; ApprovedBy: Not shown in title block; CheckedBy: Not shown in title block; Author: Not shown in title block; CompanyName: Not shown in title block; Engineer: Not shown in title block; Organization: Not shown in title block; Address1: Not shown in title block; Address2: Not shown in title block; Address3: Not shown in title block; Address4: Not shown in title block; DocumentNumber: 8; Revision: Use project parameter SCH_Rev; SheetNumber: 8; SheetTotal: 24; PageSetup: Record=PageOptions¦CenterHorizontal=True¦CenterVertical=True¦PrintScale=1.00¦XCorrection=1.00¦YCorrection=1.00¦PrintKind=0¦BorderSize=5000000¦LeftOffset=0¦BottomOffset=0¦Orientation=2¦PaperLength=1000¦PaperWidth=1000¦Scale=100¦PaperSource=15¦PrintQuality=600¦MediaType=1¦DitherType=10¦PaperKind=Letter¦PrintScaleMode=1
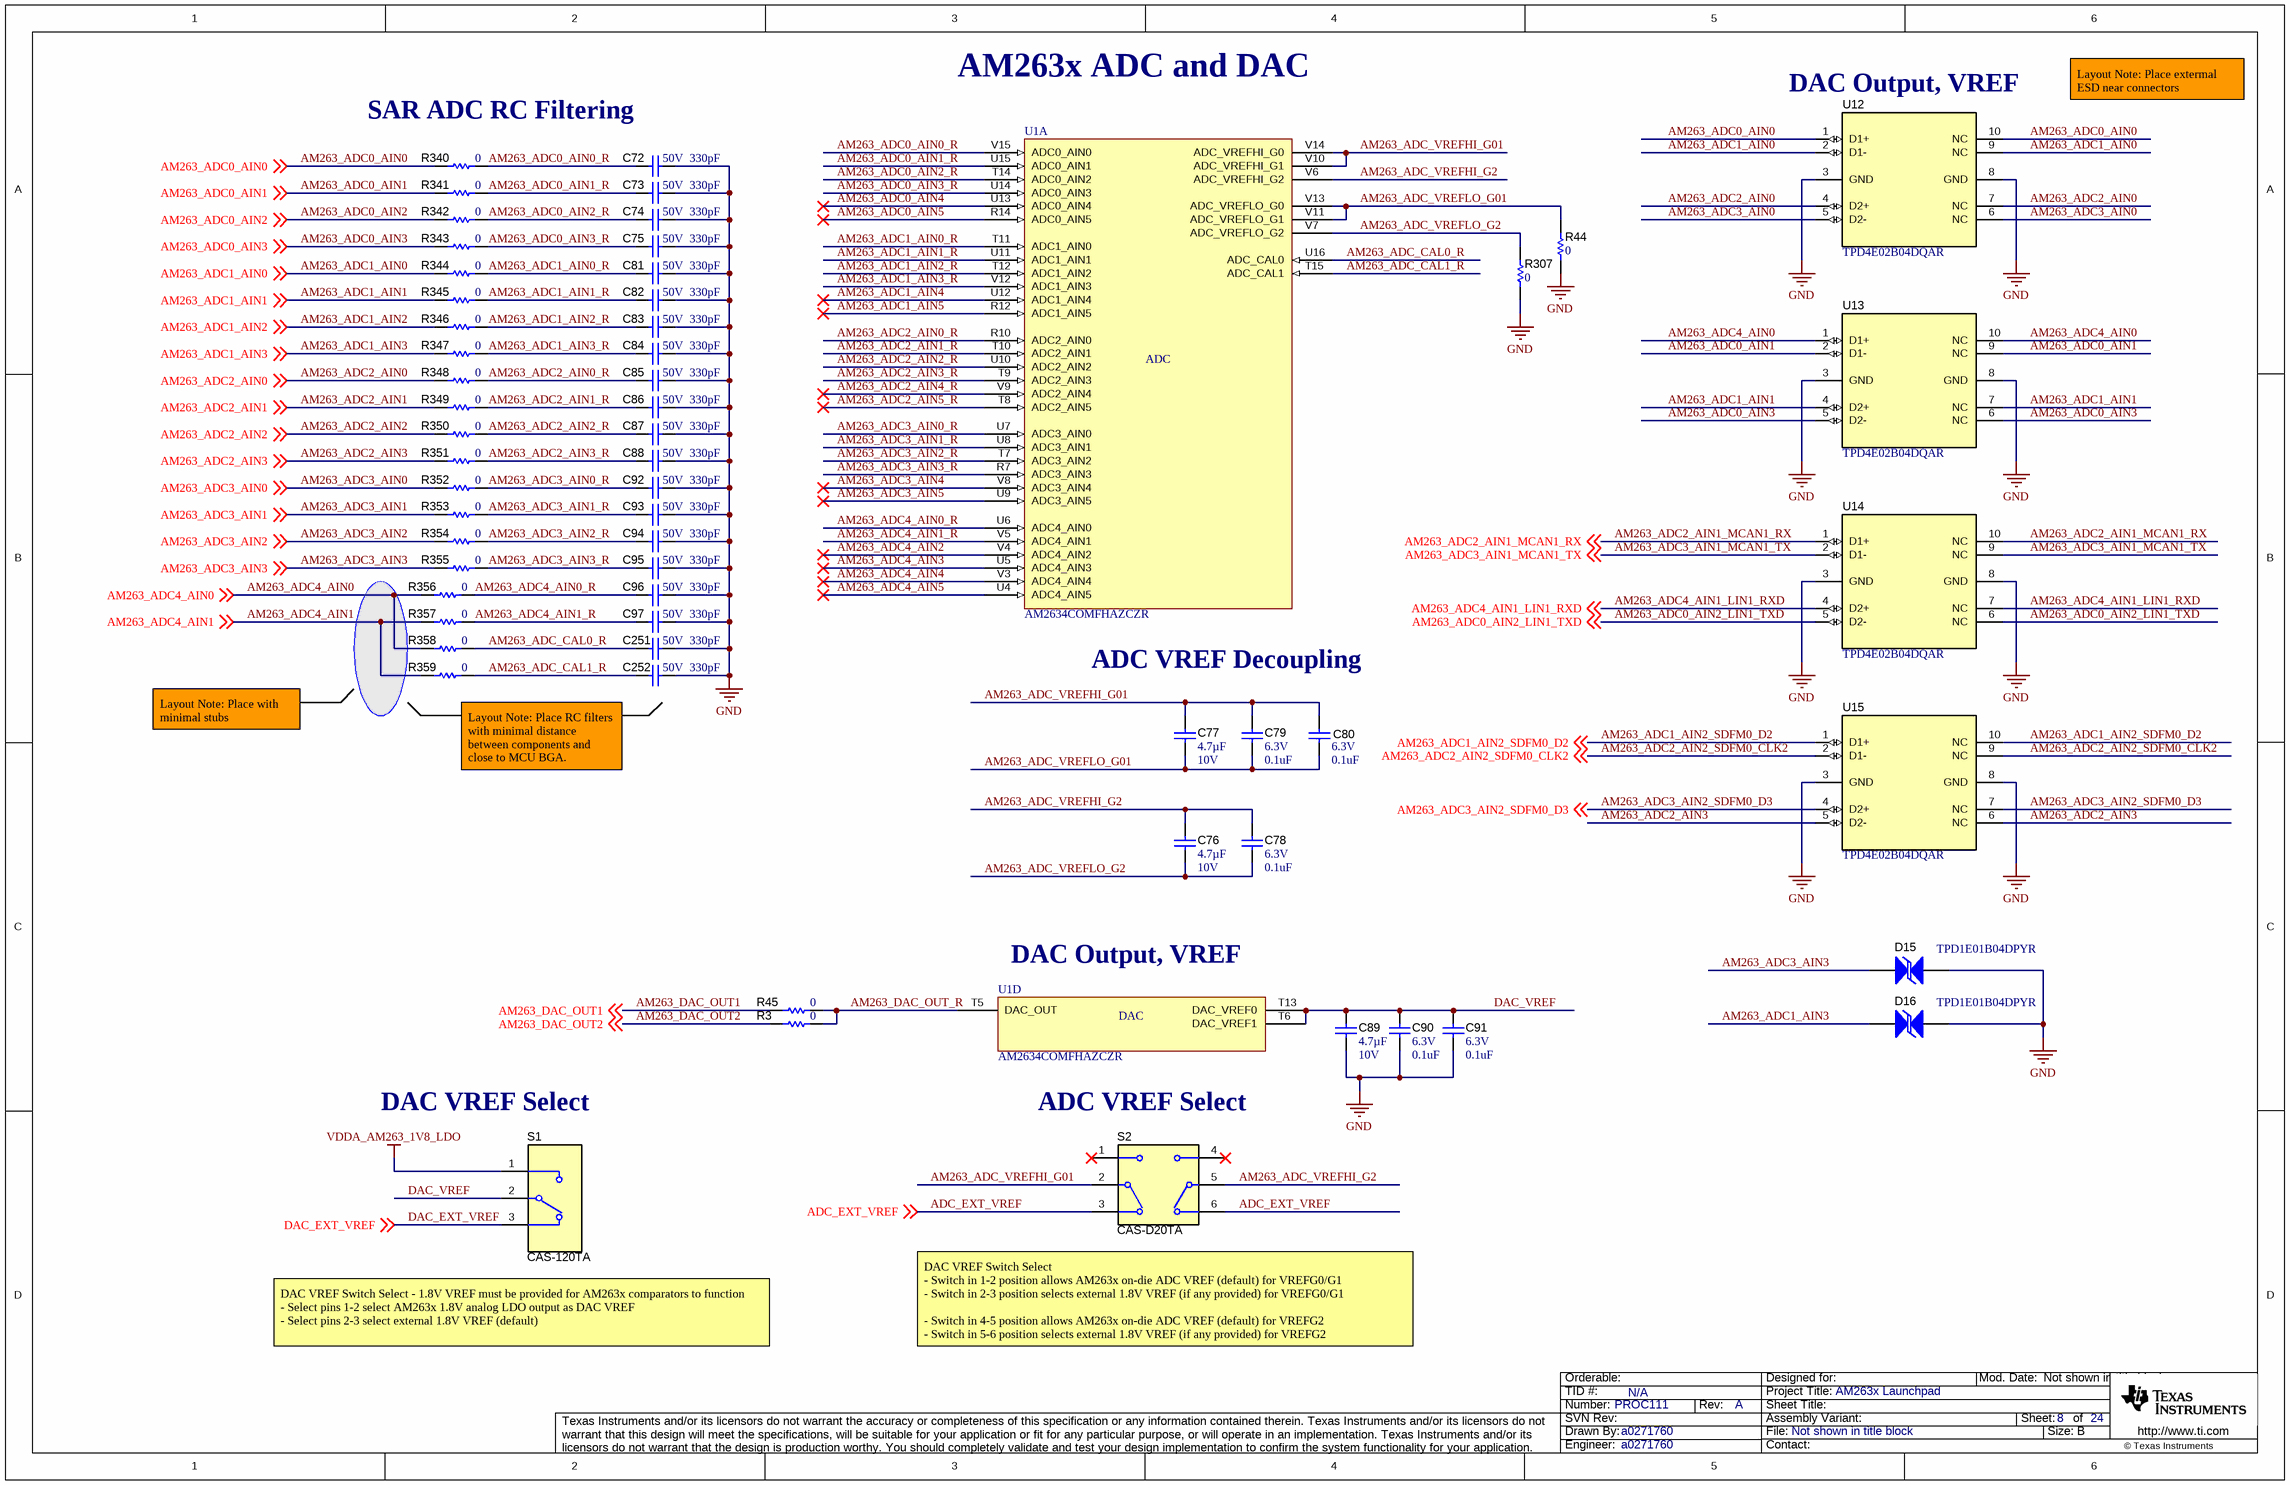
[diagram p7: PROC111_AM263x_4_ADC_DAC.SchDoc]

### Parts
C72  VDC_V: 50V  ValueDisplayed: 330pF  [0402S]  (hidden comment: GRM1555C1H331JA01D)
C73  VDC_V: 50V  ValueDisplayed: 330pF  [0402S]  (hidden comment: GRM1555C1H331JA01D)
C74  VDC_V: 50V  ValueDisplayed: 330pF  [0402S]  (hidden comment: GRM1555C1H331JA01D)
C75  VDC_V: 50V  ValueDisplayed: 330pF  [0402S]  (hidden comment: GRM1555C1H331JA01D)
C76  Cap_F: 4.7µF  VDC_V: 10V  [0603]  (hidden comment: GRM188Z71A475ME15D)
C77  Cap_F: 4.7µF  VDC_V: 10V  [0603]  (hidden comment: GRM188Z71A475ME15D)
C78  VDC_V: 6.3V  ValueDisplayed: 0.1uF  [0402]  (hidden comment: GRM155R70J104KA01D)
C79  VDC_V: 6.3V  ValueDisplayed: 0.1uF  [0402]  (hidden comment: GRM155R70J104KA01D)
C80  VDC_V: 6.3V  ValueDisplayed: 0.1uF  [0402]  (hidden comment: GRM155R70J104KA01D)
C81  VDC_V: 50V  ValueDisplayed: 330pF  [0402S]  (hidden comment: GRM1555C1H331JA01D)
C82  VDC_V: 50V  ValueDisplayed: 330pF  [0402S]  (hidden comment: GRM1555C1H331JA01D)
C83  VDC_V: 50V  ValueDisplayed: 330pF  [0402S]  (hidden comment: GRM1555C1H331JA01D)
C84  VDC_V: 50V  ValueDisplayed: 330pF  [0402S]  (hidden comment: GRM1555C1H331JA01D)
C85  VDC_V: 50V  ValueDisplayed: 330pF  [0402S]  (hidden comment: GRM1555C1H331JA01D)
C86  VDC_V: 50V  ValueDisplayed: 330pF  [0402S]  (hidden comment: GRM1555C1H331JA01D)
C87  VDC_V: 50V  ValueDisplayed: 330pF  [0402S]  (hidden comment: GRM1555C1H331JA01D)
C88  VDC_V: 50V  ValueDisplayed: 330pF  [0402S]  (hidden comment: GRM1555C1H331JA01D)
C89  Cap_F: 4.7µF  VDC_V: 10V  [0603]  (hidden comment: GRM188Z71A475ME15D)
C90  VDC_V: 6.3V  ValueDisplayed: 0.1uF  [0402]  (hidden comment: GRM155R70J104KA01D)
C91  VDC_V: 6.3V  ValueDisplayed: 0.1uF  [0402]  (hidden comment: GRM155R70J104KA01D)
C92  VDC_V: 50V  ValueDisplayed: 330pF  [0402S]  (hidden comment: GRM1555C1H331JA01D)
C93  VDC_V: 50V  ValueDisplayed: 330pF  [0402S]  (hidden comment: GRM1555C1H331JA01D)
C94  VDC_V: 50V  ValueDisplayed: 330pF  [0402S]  (hidden comment: GRM1555C1H331JA01D)
C95  VDC_V: 50V  ValueDisplayed: 330pF  [0402S]  (hidden comment: GRM1555C1H331JA01D)
C96  VDC_V: 50V  ValueDisplayed: 330pF  [0402S]  (hidden comment: GRM1555C1H331JA01D)
C97  VDC_V: 50V  ValueDisplayed: 330pF  [0402S]  (hidden comment: GRM1555C1H331JA01D)
C251  VDC_V: 50V  ValueDisplayed: 330pF  [0402S]  (hidden comment: GRM1555C1H331JA01D)
C252  VDC_V: 50V  ValueDisplayed: 330pF  [0402S]  (hidden comment: GRM1555C1H331JA01D)
D15  TPD1E01B04DPYR  [DPY0002A]
D16  TPD1E01B04DPYR  [DPY0002A]
R3  value 0  [0402L]  (hidden comment: ERJ-2GE0R00X)
R44  value 0  [0402L]  (hidden comment: ERJ-2GE0R00X)
R45  value 0  [0402L]  (hidden comment: ERJ-2GE0R00X)
R307  value 0  [0402L]  (hidden comment: ERJ-2GE0R00X)
R340  value 0  [0402L]  (hidden comment: ERJ-2GE0R00X)
R341  value 0  [0402L]  (hidden comment: ERJ-2GE0R00X)
R342  value 0  [0402L]  (hidden comment: ERJ-2GE0R00X)
R343  value 0  [0402L]  (hidden comment: ERJ-2GE0R00X)
R344  value 0  [0402L]  (hidden comment: ERJ-2GE0R00X)
R345  value 0  [0402L]  (hidden comment: ERJ-2GE0R00X)
R346  value 0  [0402L]  (hidden comment: ERJ-2GE0R00X)
R347  value 0  [0402L]  (hidden comment: ERJ-2GE0R00X)
R348  value 0  [0402L]  (hidden comment: ERJ-2GE0R00X)
R349  value 0  [0402L]  (hidden comment: ERJ-2GE0R00X)
R350  value 0  [0402L]  (hidden comment: ERJ-2GE0R00X)
R351  value 0  [0402L]  (hidden comment: ERJ-2GE0R00X)
R352  value 0  [0402L]  (hidden comment: ERJ-2GE0R00X)
R353  value 0  [0402L]  (hidden comment: ERJ-2GE0R00X)
R354  value 0  [0402L]  (hidden comment: ERJ-2GE0R00X)
R355  value 0  [0402L]  (hidden comment: ERJ-2GE0R00X)
R356  value 0  [0402L]  (hidden comment: ERJ-2GE0R00X)
R357  value 0  [0402L]  (hidden comment: ERJ-2GE0R00X)
R358  value 0  [0402L]  (hidden comment: ERJ-2GE0R00X)
R359  value 0  [0402L]  (hidden comment: ERJ-2GE0R00X)
S1  CAS-120TA  [SW_CAS-120TA]
S2  CAS-D20TA  [SW_CAS-D20TA]
U1  AM2634COMFHAZCZR  [ZCZ (S-PBGA-N324)]  (parts A,D of 13)
U12  TPD4E02B04DQAR  [DQA0010A]
U13  TPD4E02B04DQAR  [DQA0010A]
U14  TPD4E02B04DQAR  [DQA0010A]
U15  TPD4E02B04DQAR  [DQA0010A]

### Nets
GND: C72.1 C73.1 C74.1 C75.1 C81.1 C82.1 C83.1 C84.1 C85.1 C86.1 C87.1 C88.1 C89.2 C90.2 C91.2 C92.1 C93.1 C94.1 C95.1 C96.1 C97.1 C251.1 C252.1 D15.2 D16.2 R44.1 R307.1 U12.3(GND) U12.8(GND) U13.3(GND) U13.8(GND) U14.3(GND) U14.8(GND) U15.3(GND) U15.8(GND)
VDDA_AM263_1V8_LDO: S1.1
ADC_EXT_VREF: S2.3 S2.6 ; off-sheet ADC_EXT_VREF
AM263_ADC0_AIN0: R340.1 U12.1(D1+) U12.10(NC) ; off-sheet AM263_ADC0_AIN0
AM263_ADC0_AIN0_R: C72.2 R340.2 U1.V15(ADC0_AIN0)
AM263_ADC0_AIN1: R341.1 U13.2(D1-) U13.9(NC) ; off-sheet AM263_ADC0_AIN1
AM263_ADC0_AIN1_R: C73.2 R341.2 U1.U15(ADC0_AIN1)
AM263_ADC0_AIN2: R342.1 ; off-sheet AM263_ADC0_AIN2
AM263_ADC0_AIN2_LIN1_TXD: U14.5(D2-) U14.6(NC) ; off-sheet AM263_ADC0_AIN2_LIN1_TXD
AM263_ADC0_AIN2_R: C74.2 R342.2 U1.T14(ADC0_AIN2)
AM263_ADC0_AIN3: R343.1 U13.5(D2-) U13.6(NC) ; off-sheet AM263_ADC0_AIN3
AM263_ADC0_AIN3_R: C75.2 R343.2 U1.U14(ADC0_AIN3)
AM263_ADC0_AIN4: U1.U13(ADC0_AIN4)
AM263_ADC0_AIN5: U1.R14(ADC0_AIN5)
AM263_ADC1_AIN0: R344.1 U12.2(D1-) U12.9(NC) ; off-sheet AM263_ADC1_AIN0
AM263_ADC1_AIN0_R: C81.2 R344.2 U1.T11(ADC1_AIN0)
AM263_ADC1_AIN1: R345.1 U13.4(D2+) U13.7(NC) ; off-sheet AM263_ADC1_AIN1
AM263_ADC1_AIN1_R: C82.2 R345.2 U1.U11(ADC1_AIN1)
AM263_ADC1_AIN2: R346.1 ; off-sheet AM263_ADC1_AIN2
AM263_ADC1_AIN2_R: C83.2 R346.2 U1.T12(ADC1_AIN2)
AM263_ADC1_AIN2_SDFM0_D2: U15.1(D1+) U15.10(NC) ; off-sheet AM263_ADC1_AIN2_SDFM0_D2
AM263_ADC1_AIN3: D16.1 R347.1 ; off-sheet AM263_ADC1_AIN3
AM263_ADC1_AIN3_R: C84.2 R347.2 U1.V12(ADC1_AIN3)
AM263_ADC1_AIN4: U1.U12(ADC1_AIN4)
AM263_ADC1_AIN5: U1.R12(ADC1_AIN5)
AM263_ADC2_AIN0: R348.1 U12.4(D2+) U12.7(NC) ; off-sheet AM263_ADC2_AIN0
AM263_ADC2_AIN0_R: C85.2 R348.2 U1.R10(ADC2_AIN0)
AM263_ADC2_AIN1: R349.1 ; off-sheet AM263_ADC2_AIN1
AM263_ADC2_AIN1_MCAN1_RX: U14.1(D1+) U14.10(NC) ; off-sheet AM263_ADC2_AIN1_MCAN1_RX
AM263_ADC2_AIN1_R: C86.2 R349.2 U1.T10(ADC2_AIN1)
AM263_ADC2_AIN2: R350.1 ; off-sheet AM263_ADC2_AIN2
AM263_ADC2_AIN2_R: C87.2 R350.2 U1.U10(ADC2_AIN2)
AM263_ADC2_AIN2_SDFM0_CLK2: U15.2(D1-) U15.9(NC) ; off-sheet AM263_ADC2_AIN2_SDFM0_CLK2
AM263_ADC2_AIN3: R351.1 U15.5(D2-) U15.6(NC) ; off-sheet AM263_ADC2_AIN3
AM263_ADC2_AIN3_R: C88.2 R351.2 U1.T9(ADC2_AIN3)
AM263_ADC2_AIN4_R: U1.V9(ADC2_AIN4)
AM263_ADC2_AIN5_R: U1.T8(ADC2_AIN5)
AM263_ADC3_AIN0: R352.1 U12.5(D2-) U12.6(NC) ; off-sheet AM263_ADC3_AIN0
AM263_ADC3_AIN0_R: C92.2 R352.2 U1.U7(ADC3_AIN0)
AM263_ADC3_AIN1: R353.1 ; off-sheet AM263_ADC3_AIN1
AM263_ADC3_AIN1_MCAN1_TX: U14.2(D1-) U14.9(NC) ; off-sheet AM263_ADC3_AIN1_MCAN1_TX
AM263_ADC3_AIN1_R: C93.2 R353.2 U1.U8(ADC3_AIN1)
AM263_ADC3_AIN2: R354.1 ; off-sheet AM263_ADC3_AIN2
AM263_ADC3_AIN2_R: C94.2 R354.2 U1.T7(ADC3_AIN2)
AM263_ADC3_AIN2_SDFM0_D3: U15.4(D2+) U15.7(NC) ; off-sheet AM263_ADC3_AIN2_SDFM0_D3
AM263_ADC3_AIN3: D15.1 R355.1 ; off-sheet AM263_ADC3_AIN3
AM263_ADC3_AIN3_R: C95.2 R355.2 U1.R7(ADC3_AIN3)
AM263_ADC3_AIN4: U1.V8(ADC3_AIN4)
AM263_ADC3_AIN5: U1.U9(ADC3_AIN5)
AM263_ADC4_AIN0: R356.1 R358.1 U13.1(D1+) U13.10(NC) ; off-sheet AM263_ADC4_AIN0
AM263_ADC4_AIN0_R: C96.2 R356.2 U1.U6(ADC4_AIN0)
AM263_ADC4_AIN1: R357.1 R359.1 ; off-sheet AM263_ADC4_AIN1
AM263_ADC4_AIN1_LIN1_RXD: U14.4(D2+) U14.7(NC) ; off-sheet AM263_ADC4_AIN1_LIN1_RXD
AM263_ADC4_AIN1_R: C97.2 R357.2 U1.V5(ADC4_AIN1)
AM263_ADC4_AIN2: U1.V4(ADC4_AIN2)
AM263_ADC4_AIN3: U1.U5(ADC4_AIN3)
AM263_ADC4_AIN4: U1.V3(ADC4_AIN4)
AM263_ADC4_AIN5: U1.U4(ADC4_AIN5)
AM263_ADC_CAL0_R: C251.2 R358.2 U1.U16(ADC_CAL0)
AM263_ADC_CAL1_R: C252.2 R359.2 U1.T15(ADC_CAL1)
AM263_ADC_VREFHI_G01: C77.1 C79.1 C80.1 S2.2(C) U1.V10(ADC_VREFHI_G1) U1.V14(ADC_VREFHI_G0)
AM263_ADC_VREFHI_G2: C76.1 C78.1 S2.5(C) U1.V6(ADC_VREFHI_G2)
AM263_ADC_VREFLO_G01: C77.2 C79.2 C80.2 R44.2 U1.V11(ADC_VREFLO_G1) U1.V13(ADC_VREFLO_G0)
AM263_ADC_VREFLO_G2: C76.2 C78.2 R307.2 U1.V7(ADC_VREFLO_G2)
AM263_DAC_OUT1: R45.1 ; off-sheet AM263_DAC_OUT1
AM263_DAC_OUT2: R3.1 ; off-sheet AM263_DAC_OUT2
AM263_DAC_OUT_R: R3.2 R45.2 U1.T5(DAC_OUT)
DAC_EXT_VREF: S1.3 ; off-sheet DAC_EXT_VREF
DAC_VREF: C89.1 C90.1 C91.1 S1.2 U1.T6(DAC_VREF1) U1.T13(DAC_VREF0)

Not connected (* = marked no-connect by the designer): S2 1* 4*

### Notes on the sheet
- AM263x ADC and DAC
- (near U12) DAC Output, VREF
- Layout Note: Place extermal ESD near connectors
- SAR ADC RC Filtering
- ADC VREF Decoupling
- Layout Note: Place with minimal stubs
- Layout Note: Place RC filters with minimal distance between components and close to MCU BGA.
- (near U1) DAC Output, VREF
- DAC VREF Select
- ADC VREF Select
- DAC VREF Switch Select - 1.8V VREF must be provided for AM263x comparators to function
  - Select pins 1-2 select AM263x 1.8V analog LDO output as DAC VREF
  - Select pins 2-3 select external 1.8V VREF (default)
- (near S2) DAC VREF Switch Select
  - Switch in 1-2 position allows AM263x on-die ADC VREF (default) for VREFG0/G1
  - Switch in 2-3 position selects external 1.8V VREF (if any provided) for VREFG0/G1
  - Switch in 4-5 position allows AM263x on-die ADC VREF (default) for VREFG2
  - Switch in 5-6 position selects external 1.8V VREF (if any provided) for VREFG2

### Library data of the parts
C72-C75 C81-C88 C92-C97 C251 C252 = CMP-0006456-2: CAP, CERM, 330 pF, 50 V, +/- 5%, C0G/NP0, 0402; Manufacturer: MuRata; TaMin_C: -55°C; Polarized: N; SizeAreaWB_mm2: 3; U/M: EA; Value: 330pF; TaMax_C: 125°C; SizeZ_mm: 0.6; SizeX_mm: 1; SizeY_mm: 0.5; Cap_Case: 0402; AEC Category: Q200; Value1: Unknown
C76 C77 C89 = CMP-0007498-4: CAP, CERM, 4.7 uF, 10 V, +/- 20%, X7R, 0603; Manufacturer: MuRata; TaMin_C: -55°C; Polarized: N; SizeAreaWB_mm2: 4.68; Value1: Unknown; U/M: EA; Value: 4.7uF; TaMax_C: 125°C; SizeZ_mm: 1; SizeX_mm: 1.6; SizeY_mm: 0.8; SizeArea_mm2: 1.28; AEC Category: Q200
C78-C80 C90 C91 = CMP-0006623-2: as C69 on sheet PROC111_AM263x_3_QSPI_MMC
D15 D16 = CMP-0073602-3: 1-Channel ESD Protection Diode for USB Type-C and Thunderbolt 3, DPY0002A (X1SON-2); Alternate Manufacturer: Texas Instruments; Alternate PartNumber: TPD1E01B04DPYT; AEC Category: Q200; SizeArea_mm2: 0.6; CompType: IC; SizeAreaWB_mm2: 3.2; SizeZ_mm: 0.45; Rating: Catalog; SizeX_mm: 1.0
R3 R44 R45 R307 R340-R359 = CMP-0026992-3: as R4 on sheet PROC111_AM263x_2_Clock_Reset_Boot_JTAG
S1 = CMP-0002139-2: Switch, Slide, SPDT  100mA, SMT; Manufacturer: Copal Electronics; CurrentRating_mA: 100A; SwitchFunction: On-On; VDC_V: 6V; PositionCount: 1
S2 = CMP-0002233-1: Switch, Dual SPDT,  2 Pos, 0.1A, 6VDC, SMD; Manufacturer: Copal Electronics; CurrentRating_mA: 100A; SwitchFunction: On-On; VDC_V: 6V; PositionCount: 2
U1 = AM263x: as U1 on sheet PROC111_AM263x_2_Clock_Reset_Boot_JTAG
U12-U15 = CMP-0073612-3: 4-Channel ESD Protection Diode for USB Type-C and HDMI 2.0, DQA0010A (USON-10); Alternate Manufacturer: Texas Instruments; Green_Lifecycle: Active; SizeAreaWB_mm2: 7.0; Green_REACh: Passed; SizeZ_mm: 0.55; SizeX_mm: 1.0; SizeY_mm: 2.5; CompType: IC; AEC Category: Q200; AEC Qualified: Y

## Sheet PROC111_AM263x_5_ePWM_eQEP_FSI.SchDoc
size 431 x 279 mm; Date: Not shown in title block; ApprovedBy: Not shown in title block; CheckedBy: Not shown in title block; Author: Not shown in title block; CompanyName: Not shown in title block; Engineer: Not shown in title block; Organization: Not shown in title block; Address1: Not shown in title block; Address2: Not shown in title block; Address3: Not shown in title block; Address4: Not shown in title block; DocumentNumber: 9; Revision: Use project parameter SCH_Rev; SheetNumber: 9; SheetTotal: 24; PageSetup: Record=PageOptions¦CenterHorizontal=True¦CenterVertical=True¦PrintScale=1.00¦XCorrection=1.00¦YCorrection=1.00¦PrintKind=0¦BorderSize=5000000¦LeftOffset=0¦BottomOffset=0¦Orientation=2¦PaperLength=1000¦PaperWidth=1000¦Scale=100¦PaperSource=15¦PrintQuality=600¦MediaType=1¦DitherType=10¦PaperKind=Letter¦PrintScaleMode=1
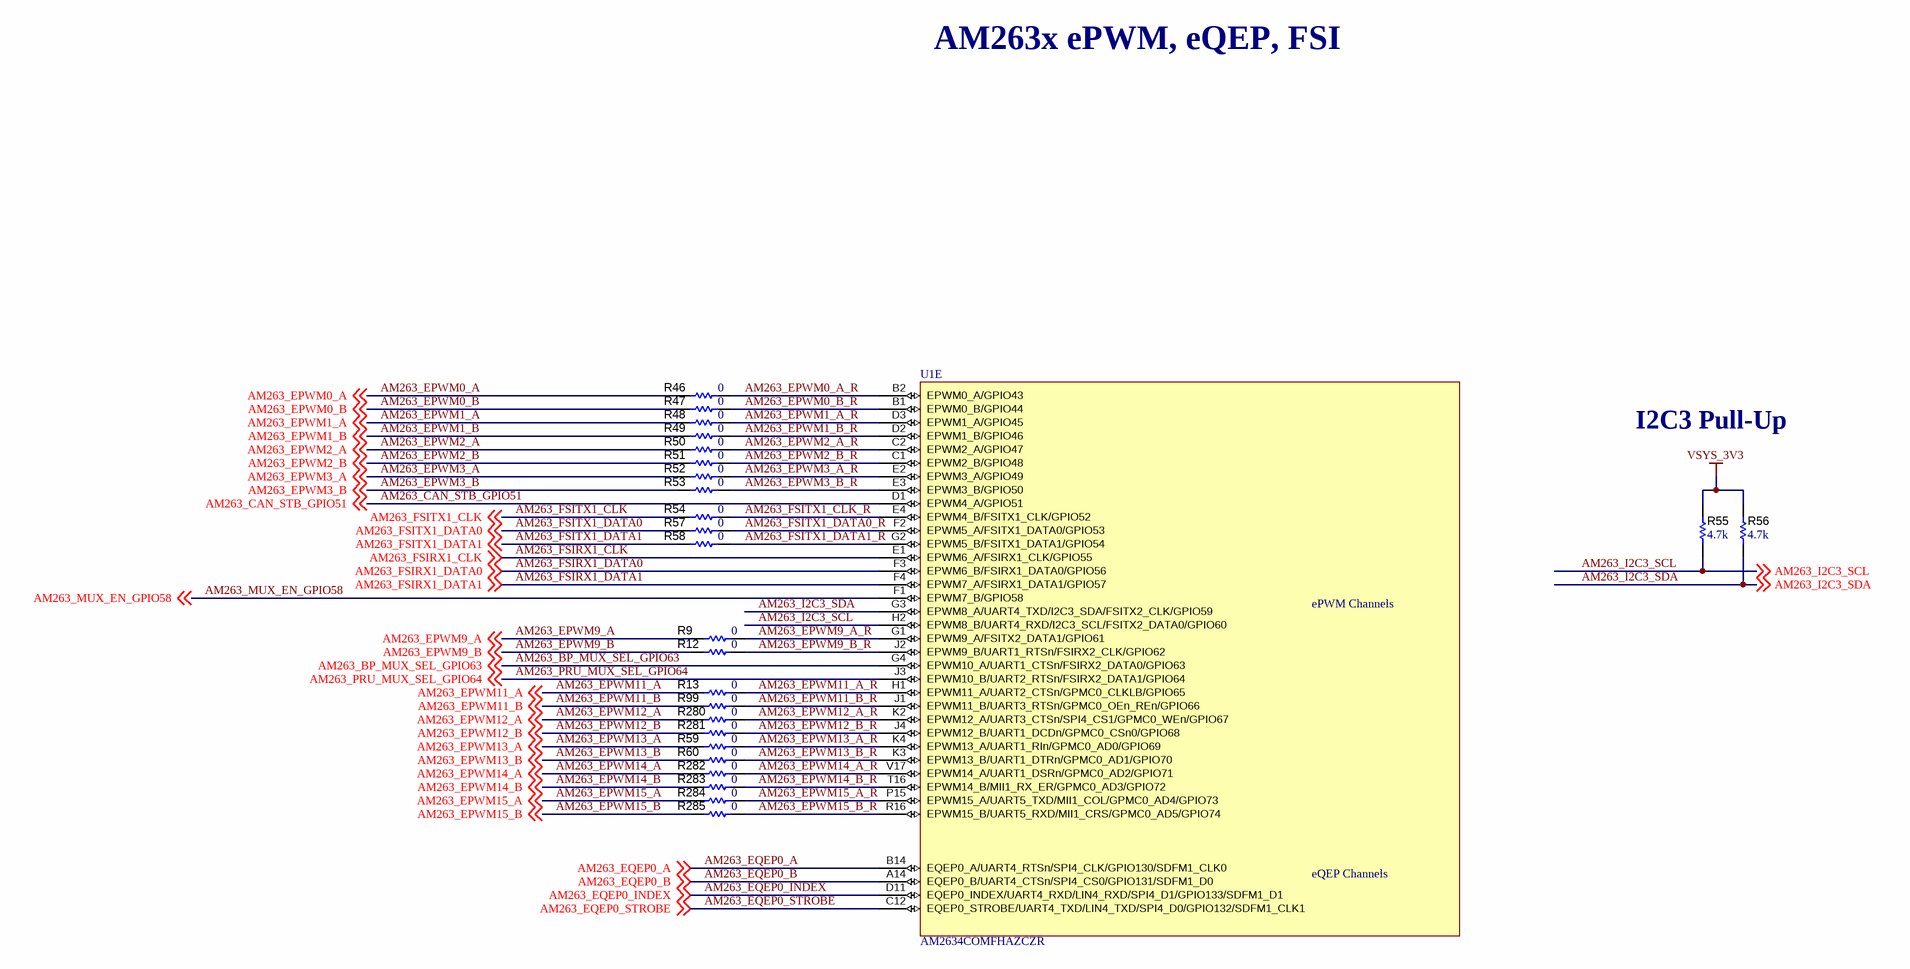
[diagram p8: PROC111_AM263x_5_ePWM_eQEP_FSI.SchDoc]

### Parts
R9  value 0  [0402L]  (hidden comment: ERJ-2GE0R00X)
R12  value 0  [0402L]  (hidden comment: ERJ-2GE0R00X)
R13  value 0  [0402L]  (hidden comment: ERJ-2GE0R00X)
R46  value 0  [0402L]  (hidden comment: ERJ-2GE0R00X)
R47  value 0  [0402L]  (hidden comment: ERJ-2GE0R00X)
R48  value 0  [0402L]  (hidden comment: ERJ-2GE0R00X)
R49  value 0  [0402L]  (hidden comment: ERJ-2GE0R00X)
R50  value 0  [0402L]  (hidden comment: ERJ-2GE0R00X)
R51  value 0  [0402L]  (hidden comment: ERJ-2GE0R00X)
R52  value 0  [0402L]  (hidden comment: ERJ-2GE0R00X)
R53  value 0  [0402L]  (hidden comment: ERJ-2GE0R00X)
R54  value 0  [0402L]  (hidden comment: ERJ-2GE0R00X)
R55  ValueDisplayed: 4.7k  [0402]  (hidden comment: CRCW04024K70JNED)
R56  ValueDisplayed: 4.7k  [0402]  (hidden comment: CRCW04024K70JNED)
R57  value 0  [0402L]  (hidden comment: ERJ-2GE0R00X)
R58  value 0  [0402L]  (hidden comment: ERJ-2GE0R00X)
R59  value 0  [0402L]  (hidden comment: ERJ-2GE0R00X)
R60  value 0  [0402L]  (hidden comment: ERJ-2GE0R00X)
R99  value 0  [0402L]  (hidden comment: ERJ-2GE0R00X)
R280  value 0  [0402L]  (hidden comment: ERJ-2GE0R00X)
R281  value 0  [0402L]  (hidden comment: ERJ-2GE0R00X)
R282  value 0  [0402L]  (hidden comment: ERJ-2GE0R00X)
R283  value 0  [0402L]  (hidden comment: ERJ-2GE0R00X)
R284  value 0  [0402L]  (hidden comment: ERJ-2GE0R00X)
R285  value 0  [0402L]  (hidden comment: ERJ-2GE0R00X)
U1  AM2634COMFHAZCZR  [ZCZ (S-PBGA-N324)]  (part E of 13)

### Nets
VSYS_3V3: R55.2 R56.2
AM263_BP_MUX_SEL_GPIO63: U1.G4(EPWM10_A/UART1_CTSn/FSIRX2_DATA0/GPIO63) ; off-sheet AM263_BP_MUX_SEL_GPIO63
AM263_CAN_STB_GPIO51: U1.D1(EPWM4_A/GPIO51) ; off-sheet AM263_CAN_STB_GPIO51
AM263_EPWM0_A: R46.1 ; off-sheet AM263_EPWM0_A
AM263_EPWM0_A_R: R46.2 U1.B2(EPWM0_A/GPIO43)
AM263_EPWM0_B: R47.1 ; off-sheet AM263_EPWM0_B
AM263_EPWM0_B_R: R47.2 U1.B1(EPWM0_B/GPIO44)
AM263_EPWM1_A: R48.1 ; off-sheet AM263_EPWM1_A
AM263_EPWM1_A_R: R48.2 U1.D3(EPWM1_A/GPIO45)
AM263_EPWM1_B: R49.1 ; off-sheet AM263_EPWM1_B
AM263_EPWM1_B_R: R49.2 U1.D2(EPWM1_B/GPIO46)
AM263_EPWM2_A: R50.1 ; off-sheet AM263_EPWM2_A
AM263_EPWM2_A_R: R50.2 U1.C2(EPWM2_A/GPIO47)
AM263_EPWM2_B: R51.1 ; off-sheet AM263_EPWM2_B
AM263_EPWM2_B_R: R51.2 U1.C1(EPWM2_B/GPIO48)
AM263_EPWM3_A: R52.1 ; off-sheet AM263_EPWM3_A
AM263_EPWM3_A_R: R52.2 U1.E2(EPWM3_A/GPIO49)
AM263_EPWM3_B: R53.1 ; off-sheet AM263_EPWM3_B
AM263_EPWM3_B_R: R53.2 U1.E3(EPWM3_B/GPIO50)
AM263_EPWM9_A: R9.1 ; off-sheet AM263_EPWM9_A
AM263_EPWM9_A_R: R9.2 U1.G1(EPWM9_A/FSITX2_DATA1/GPIO61)
AM263_EPWM9_B: R12.1 ; off-sheet AM263_EPWM9_B
AM263_EPWM9_B_R: R12.2 U1.J2(EPWM9_B/UART1_RTSn/FSIRX2_CLK/GPIO62)
AM263_EPWM11_A: R13.1 ; off-sheet AM263_EPWM11_A
AM263_EPWM11_A_R: R13.2 U1.H1(EPWM11_A/UART2_CTSn/GPMC0_CLKLB/GPIO65)
AM263_EPWM11_B: R99.1 ; off-sheet AM263_EPWM11_B
AM263_EPWM11_B_R: R99.2 U1.J1(EPWM11_B/UART3_RTSn/GPMC0_OEn_REn/GPIO66)
AM263_EPWM12_A: R280.1 ; off-sheet AM263_EPWM12_A
AM263_EPWM12_A_R: R280.2 U1.K2(EPWM12_A/UART3_CTSn/SPI4_CS1/GPMC0_WEn/GPIO67)
AM263_EPWM12_B: R281.1 ; off-sheet AM263_EPWM12_B
AM263_EPWM12_B_R: R281.2 U1.J4(EPWM12_B/UART1_DCDn/GPMC0_CSn0/GPIO68)
AM263_EPWM13_A: R59.1 ; off-sheet AM263_EPWM13_A
AM263_EPWM13_A_R: R59.2 U1.K4(EPWM13_A/UART1_RIn/GPMC0_AD0/GPIO69)
AM263_EPWM13_B: R60.1 ; off-sheet AM263_EPWM13_B
AM263_EPWM13_B_R: R60.2 U1.K3(EPWM13_B/UART1_DTRn/GPMC0_AD1/GPIO70)
AM263_EPWM14_A: R282.1 ; off-sheet AM263_EPWM14_A
AM263_EPWM14_A_R: R282.2 U1.V17(EPWM14_A/UART1_DSRn/GPMC0_AD2/GPIO71)
AM263_EPWM14_B: R283.1 ; off-sheet AM263_EPWM14_B
AM263_EPWM14_B_R: R283.2 U1.T16(EPWM14_B/MII1_RX_ER/GPMC0_AD3/GPIO72)
AM263_EPWM15_A: R284.1 ; off-sheet AM263_EPWM15_A
AM263_EPWM15_A_R: R284.2 U1.P15(EPWM15_A/UART5_TXD/MII1_COL/GPMC0_AD4/GPIO73)
AM263_EPWM15_B: R285.1 ; off-sheet AM263_EPWM15_B
AM263_EPWM15_B_R: R285.2 U1.R16(EPWM15_B/UART5_RXD/MII1_CRS/GPMC0_AD5/GPIO74)
AM263_EQEP0_A: U1.B14(EQEP0_A/UART4_RTSn/SPI4_CLK/GPIO130/SDFM1_CLK0) ; off-sheet AM263_EQEP0_A
AM263_EQEP0_B: U1.A14(EQEP0_B/UART4_CTSn/SPI4_CS0/GPIO131/SDFM1_D0) ; off-sheet AM263_EQEP0_B
AM263_EQEP0_INDEX: U1.D11(EQEP0_INDEX/UART4_RXD/LIN4_RXD/SPI4_D1/GPIO133/SDFM1_D1) ; off-sheet AM263_EQEP0_INDEX
AM263_EQEP0_STROBE: U1.C12(EQEP0_STROBE/UART4_TXD/LIN4_TXD/SPI4_D0/GPIO132/SDFM1_CLK1) ; off-sheet AM263_EQEP0_STROBE
AM263_FSIRX1_CLK: U1.E1(EPWM6_A/FSIRX1_CLK/GPIO55) ; off-sheet AM263_FSIRX1_CLK
AM263_FSIRX1_DATA0: U1.F3(EPWM6_B/FSIRX1_DATA0/GPIO56) ; off-sheet AM263_FSIRX1_DATA0
AM263_FSIRX1_DATA1: U1.F4(EPWM7_A/FSIRX1_DATA1/GPIO57) ; off-sheet AM263_FSIRX1_DATA1
AM263_FSITX1_CLK: R54.1 ; off-sheet AM263_FSITX1_CLK
AM263_FSITX1_CLK_R: R54.2 U1.E4(EPWM4_B/FSITX1_CLK/GPIO52)
AM263_FSITX1_DATA0: R57.1 ; off-sheet AM263_FSITX1_DATA0
AM263_FSITX1_DATA0_R: R57.2 U1.F2(EPWM5_A/FSITX1_DATA0/GPIO53)
AM263_FSITX1_DATA1: R58.1 ; off-sheet AM263_FSITX1_DATA1
AM263_FSITX1_DATA1_R: R58.2 U1.G2(EPWM5_B/FSITX1_DATA1/GPIO54)
AM263_I2C3_SCL: R55.1 U1.H2(EPWM8_B/UART4_RXD/I2C3_SCL/FSITX2_DATA0/GPIO60) ; off-sheet AM263_I2C3_SCL
AM263_I2C3_SDA: R56.1 U1.G3(EPWM8_A/UART4_TXD/I2C3_SDA/FSITX2_CLK/GPIO59) ; off-sheet AM263_I2C3_SDA
AM263_MUX_EN_GPIO58: U1.F1(EPWM7_B/GPIO58) ; off-sheet AM263_MUX_EN_GPIO58
AM263_PRU_MUX_SEL_GPIO64: U1.J3(EPWM10_B/UART2_RTSn/FSIRX2_DATA1/GPIO64) ; off-sheet AM263_PRU_MUX_SEL_GPIO64

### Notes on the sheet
- AM263x ePWM, eQEP, FSI
- I2C3 Pull-Up

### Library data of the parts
R9 R12 R13 R46-R54 R57-R60 R99 R280-R285 = CMP-0026992-3: as R4 on sheet PROC111_AM263x_2_Clock_Reset_Boot_JTAG
R55 R56 = CMP-0026938-5: as R175 on sheet PROC111_AM263x_Serial_Connectivity
U1 = AM263x: as U1 on sheet PROC111_AM263x_2_Clock_Reset_Boot_JTAG

## Sheet PROC111_AM263x_6_RGMII_MII.SchDoc
size 431 x 279 mm; Date: Not shown in title block; ApprovedBy: Not shown in title block; CheckedBy: Not shown in title block; Author: Not shown in title block; CompanyName: Not shown in title block; Engineer: Not shown in title block; Organization: Not shown in title block; Address1: Not shown in title block; Address2: Not shown in title block; Address3: Not shown in title block; Address4: Not shown in title block; DocumentNumber: 10; Revision: Use project parameter SCH_Rev; SheetNumber: 10; SheetTotal: 24; PageSetup: Record=PageOptions¦CenterHorizontal=True¦CenterVertical=True¦PrintScale=1.00¦XCorrection=1.00¦YCorrection=1.00¦PrintKind=0¦BorderSize=5000000¦LeftOffset=0¦BottomOffset=0¦Orientation=2¦PaperLength=1000¦PaperWidth=1000¦Scale=100¦PaperSource=15¦PrintQuality=600¦MediaType=1¦DitherType=10¦PaperKind=Letter¦PrintScaleMode=1
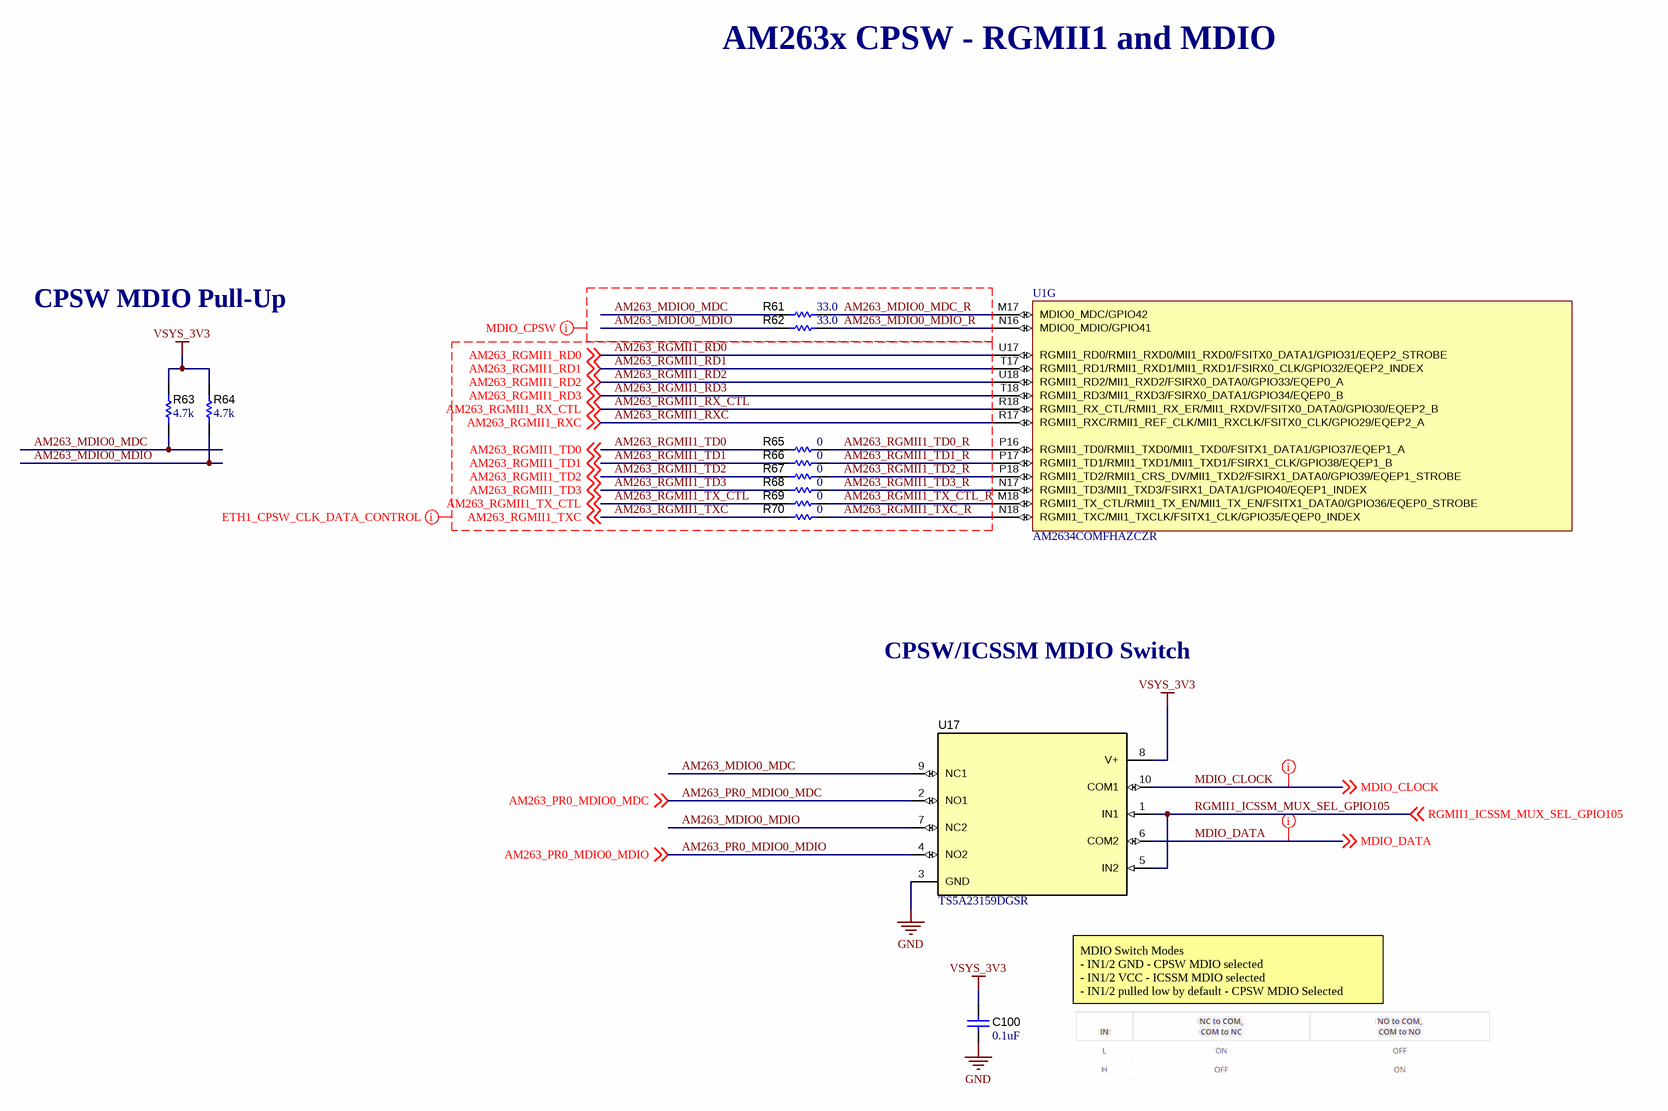
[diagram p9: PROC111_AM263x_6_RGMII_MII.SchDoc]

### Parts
C100  ValueDisplayed: 0.1uF  [0402]  (hidden comment: GRM155R71E104KE14D)
R61  ValueDisplayed: 33.0  [0402L]  (hidden comment: ERJ-2RKF33R0X)
R62  ValueDisplayed: 33.0  [0402L]  (hidden comment: ERJ-2RKF33R0X)
R63  ValueDisplayed: 4.7k  [0402]  (hidden comment: CRCW04024K70JNED)
R64  ValueDisplayed: 4.7k  [0402]  (hidden comment: CRCW04024K70JNED)
R65  value 0  [0402L]  (hidden comment: ERJ-2GE0R00X)
R66  value 0  [0402L]  (hidden comment: ERJ-2GE0R00X)
R67  value 0  [0402L]  (hidden comment: ERJ-2GE0R00X)
R68  value 0  [0402L]  (hidden comment: ERJ-2GE0R00X)
R69  value 0  [0402L]  (hidden comment: ERJ-2GE0R00X)
R70  value 0  [0402L]  (hidden comment: ERJ-2GE0R00X)
U1  AM2634COMFHAZCZR  [ZCZ (S-PBGA-N324)]  (part G of 13)
U17  TS5A23159DGSR  [DGS0010A_N]

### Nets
GND: C100.1 U17.3(GND)
VSYS_3V3: C100.2 R63.2 R64.2 U17.8(V+)
AM263_MDIO0_MDC: R61.1 R63.1 U17.9(NC1)
AM263_MDIO0_MDC_R: R61.2 U1.M17(MDIO0_MDC/GPIO42)
AM263_MDIO0_MDIO: R62.1 R64.1 U17.7(NC2)
AM263_MDIO0_MDIO_R: R62.2 U1.N16(MDIO0_MDIO/GPIO41)
AM263_PR0_MDIO0_MDC: U17.2(NO1) ; off-sheet AM263_PR0_MDIO0_MDC
AM263_PR0_MDIO0_MDIO: U17.4(NO2) ; off-sheet AM263_PR0_MDIO0_MDIO
AM263_RGMII1_RD0: U1.U17(RGMII1_RD0/RMII1_RXD0/MII1_RXD0/FSITX0_DATA1/GPIO31/EQEP2_STROBE) ; off-sheet AM263_RGMII1_RD0
AM263_RGMII1_RD1: U1.T17(RGMII1_RD1/RMII1_RXD1/MII1_RXD1/FSIRX0_CLK/GPIO32/EQEP2_INDEX) ; off-sheet AM263_RGMII1_RD1
AM263_RGMII1_RD2: U1.U18(RGMII1_RD2/MII1_RXD2/FSIRX0_DATA0/GPIO33/EQEP0_A) ; off-sheet AM263_RGMII1_RD2
AM263_RGMII1_RD3: U1.T18(RGMII1_RD3/MII1_RXD3/FSIRX0_DATA1/GPIO34/EQEP0_B) ; off-sheet AM263_RGMII1_RD3
AM263_RGMII1_RX_CTL: U1.R18(RGMII1_RX_CTL/RMII1_RX_ER/MII1_RXDV/FSITX0_DATA0/GPIO30/EQEP2_B) ; off-sheet AM263_RGMII1_RX_CTL
AM263_RGMII1_RXC: U1.R17(RGMII1_RXC/RMII1_REF_CLK/MII1_RXCLK/FSITX0_CLK/GPIO29/EQEP2_A) ; off-sheet AM263_RGMII1_RXC
AM263_RGMII1_TD0: R65.1 ; off-sheet AM263_RGMII1_TD0
AM263_RGMII1_TD0_R: R65.2 U1.P16(RGMII1_TD0/RMII1_TXD0/MII1_TXD0/FSITX1_DATA1/GPIO37/EQEP1_A)
AM263_RGMII1_TD1: R66.1 ; off-sheet AM263_RGMII1_TD1
AM263_RGMII1_TD1_R: R66.2 U1.P17(RGMII1_TD1/RMII1_TXD1/MII1_TXD1/FSIRX1_CLK/GPIO38/EQEP1_B)
AM263_RGMII1_TD2: R67.1 ; off-sheet AM263_RGMII1_TD2
AM263_RGMII1_TD2_R: R67.2 U1.P18(RGMII1_TD2/RMII1_CRS_DV/MII1_TXD2/FSIRX1_DATA0/GPIO39/EQEP1_STROBE)
AM263_RGMII1_TD3: R68.1 ; off-sheet AM263_RGMII1_TD3
AM263_RGMII1_TD3_R: R68.2 U1.N17(RGMII1_TD3/MII1_TXD3/FSIRX1_DATA1/GPIO40/EQEP1_INDEX)
AM263_RGMII1_TX_CTL: R69.1 ; off-sheet AM263_RGMII1_TX_CTL
AM263_RGMII1_TX_CTL_R: R69.2 U1.M18(RGMII1_TX_CTL/RMII1_TX_EN/MII1_TX_EN/FSITX1_DATA0/GPIO36/EQEP0_STROBE)
AM263_RGMII1_TXC: R70.1 ; off-sheet AM263_RGMII1_TXC
AM263_RGMII1_TXC_R: R70.2 U1.N18(RGMII1_TXC/MII1_TXCLK/FSITX1_CLK/GPIO35/EQEP0_INDEX)
MDIO_CLOCK: U17.10(COM1) ; off-sheet MDIO_CLOCK
MDIO_DATA: U17.6(COM2) ; off-sheet MDIO_DATA
RGMII1_ICSSM_MUX_SEL_GPIO105: U17.1(IN1) U17.5(IN2) ; off-sheet RGMII1_ICSSM_MUX_SEL_GPIO105

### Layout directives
mark named ETH1_CPSW_CLK_DATA_CONTROL: AM263_RGMII1_RD0, AM263_RGMII1_RD1, AM263_RGMII1_RD2, AM263_RGMII1_RD3, AM263_RGMII1_RX_CTL, AM263_RGMII1_RXC, AM263_RGMII1_TD0, AM263_RGMII1_TD0_R, AM263_RGMII1_TD1, AM263_RGMII1_TD1_R, AM263_RGMII1_TD2, AM263_RGMII1_TD2_R, AM263_RGMII1_TD3, AM263_RGMII1_TD3_R, AM263_RGMII1_TX_CTL, AM263_RGMII1_TX_CTL_R, AM263_RGMII1_TXC, AM263_RGMII1_TXC_R
mark named MDIO_CPSW: AM263_MDIO0_MDC, AM263_MDIO0_MDC_R, AM263_MDIO0_MDIO, AM263_MDIO0_MDIO_R
mark named MDIO: MDIO_CLOCK, MDIO_DATA

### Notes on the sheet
- AM263x CPSW - RGMII1 and MDIO
- CPSW MDIO Pull-Up
- CPSW/ICSSM MDIO Switch
- MDIO Switch Modes
  - IN1/2 GND - CPSW MDIO selected
  - IN1/2 VCC - ICSSM MDIO selected
  - IN1/2 pulled low by default - CPSW MDIO Selected

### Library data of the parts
C100 = CMP-0006659-2: as C57 on sheet PROC111_AM263x_2_Clock_Reset_Boot_JTAG
R61 R62 = CMP-0026696-1: as R27 on sheet PROC111_AM263x_3_QSPI_MMC
R63 R64 = CMP-0026938-5: as R175 on sheet PROC111_AM263x_Serial_Connectivity
R65-R70 = CMP-0026992-3: as R4 on sheet PROC111_AM263x_2_Clock_Reset_Boot_JTAG
U1 = AM263x: as U1 on sheet PROC111_AM263x_2_Clock_Reset_Boot_JTAG
U17 = CMP-0067419-2: 2-Channel, 2:1 Analog Switch with Low On-State Resistance (1ohm) and Powered Off Protection, DGS0010A (VSSOP-10); Alternate PartNumber: TS5A23159DGST; Alternate Manufacturer: Texas Instruments; Green_Lifecycle: Active; SizeAreaWB_mm2: 23.6; Green_REACh: Passed; SizeZ_mm: 1.1; SizeX_mm: 4.9; SizeY_mm: 3.0; SizeArea_mm2: 14.7; CompType: IC; AEC Category: Q200; AEC Qualified: N; Rating: Catalog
